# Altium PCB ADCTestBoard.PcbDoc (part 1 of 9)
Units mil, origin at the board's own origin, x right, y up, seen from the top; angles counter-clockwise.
Board outline 11022.62 x 9187 mil, 8 copper layers (TopLayer, InternalPlane1, InternalPlane2, InternalPlane3, InternalPlane4, InternalPlane5, MidLayer1, BottomLayer), stack 103.8 mil thick; 1282 components, 637 nets, 4473 pads, 1306 vias.
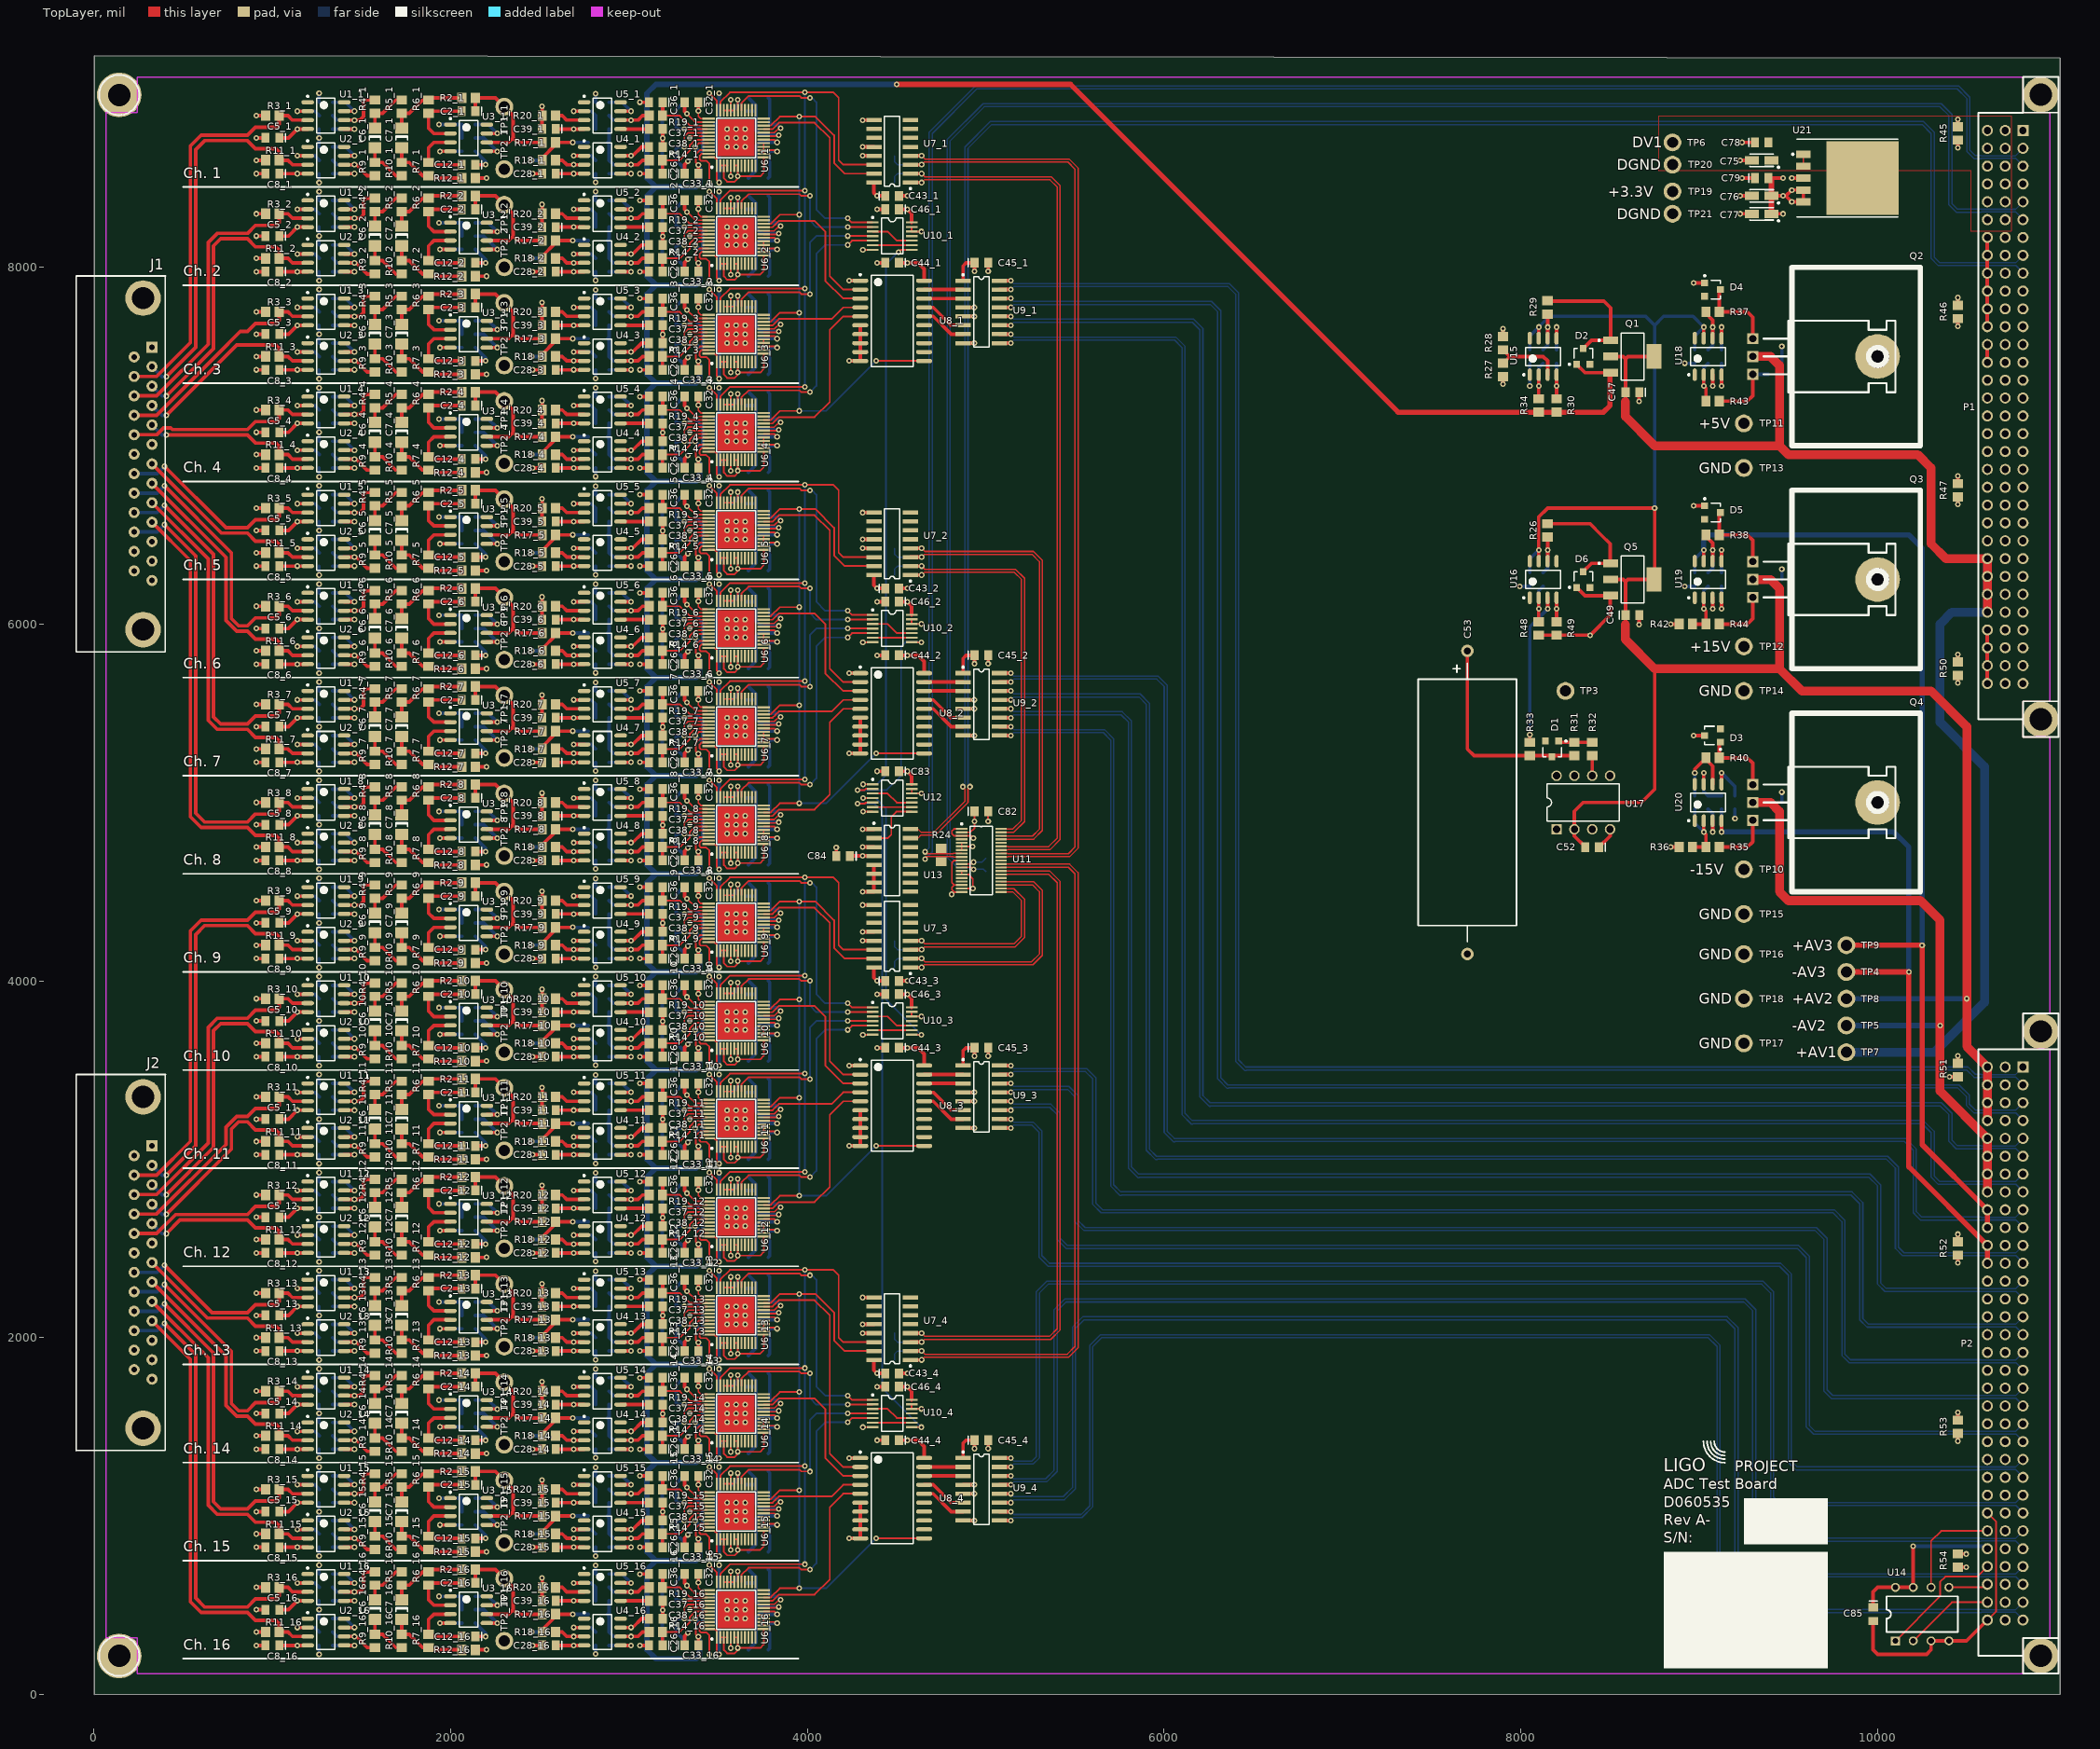
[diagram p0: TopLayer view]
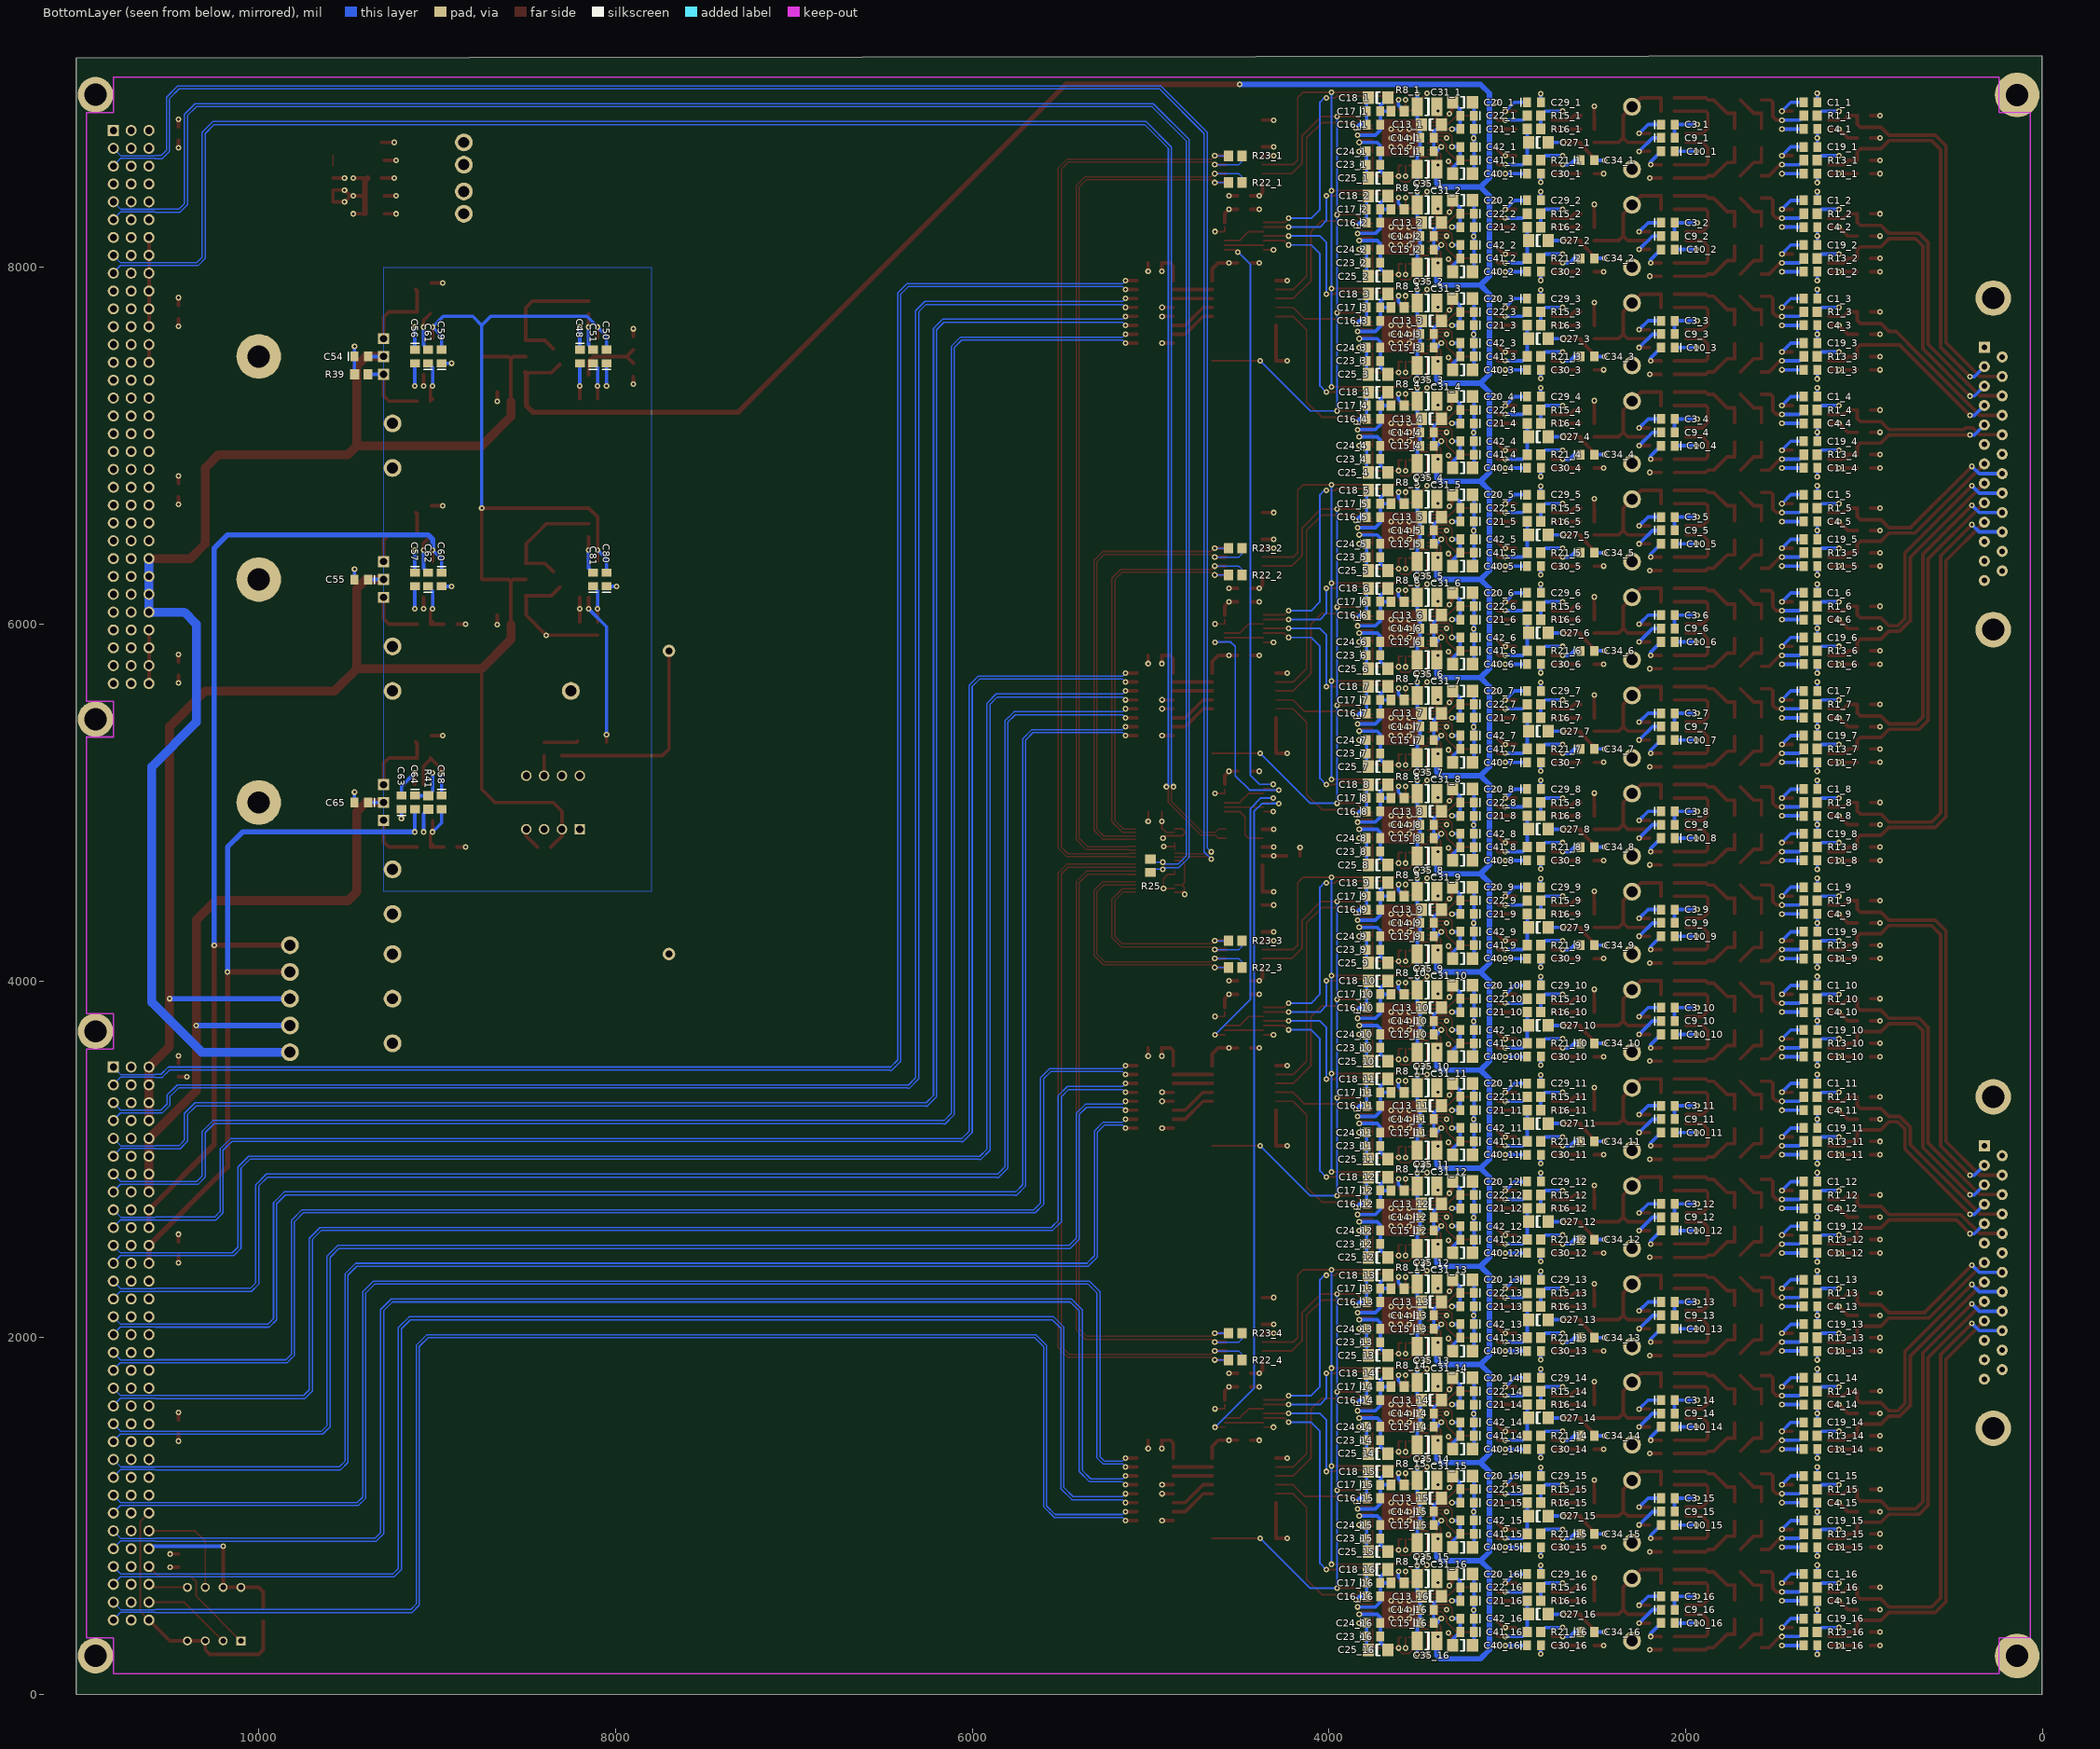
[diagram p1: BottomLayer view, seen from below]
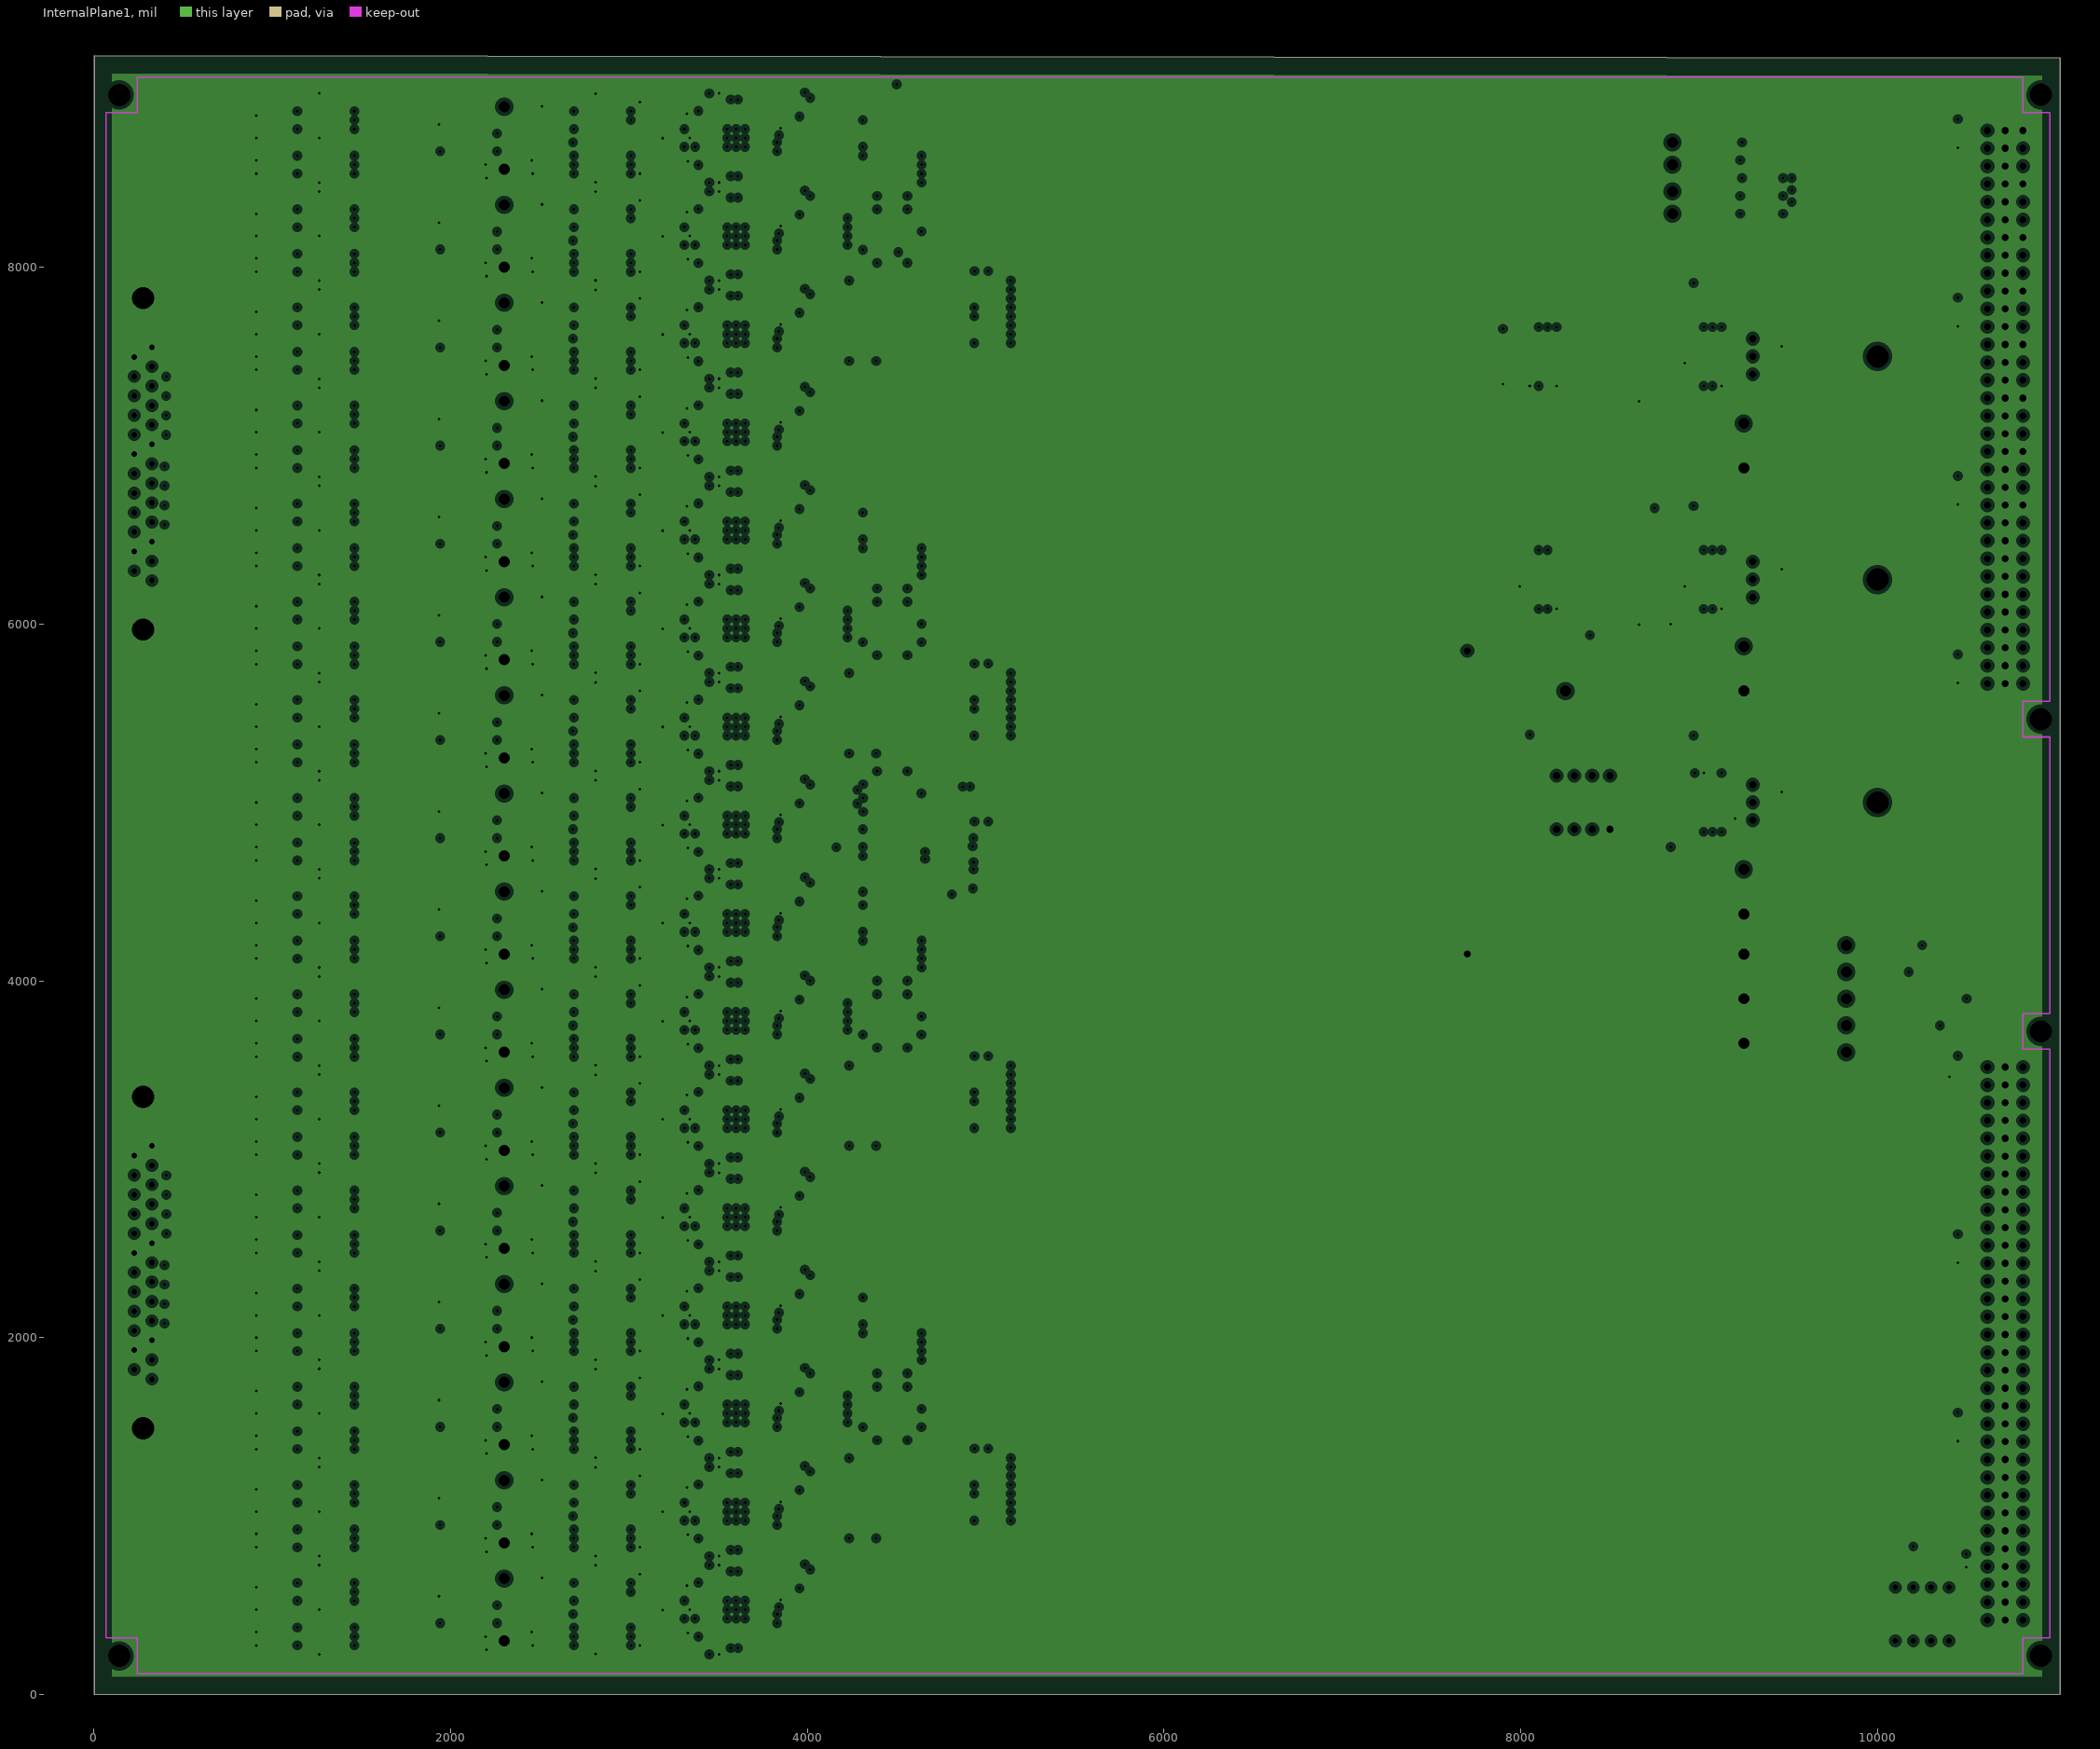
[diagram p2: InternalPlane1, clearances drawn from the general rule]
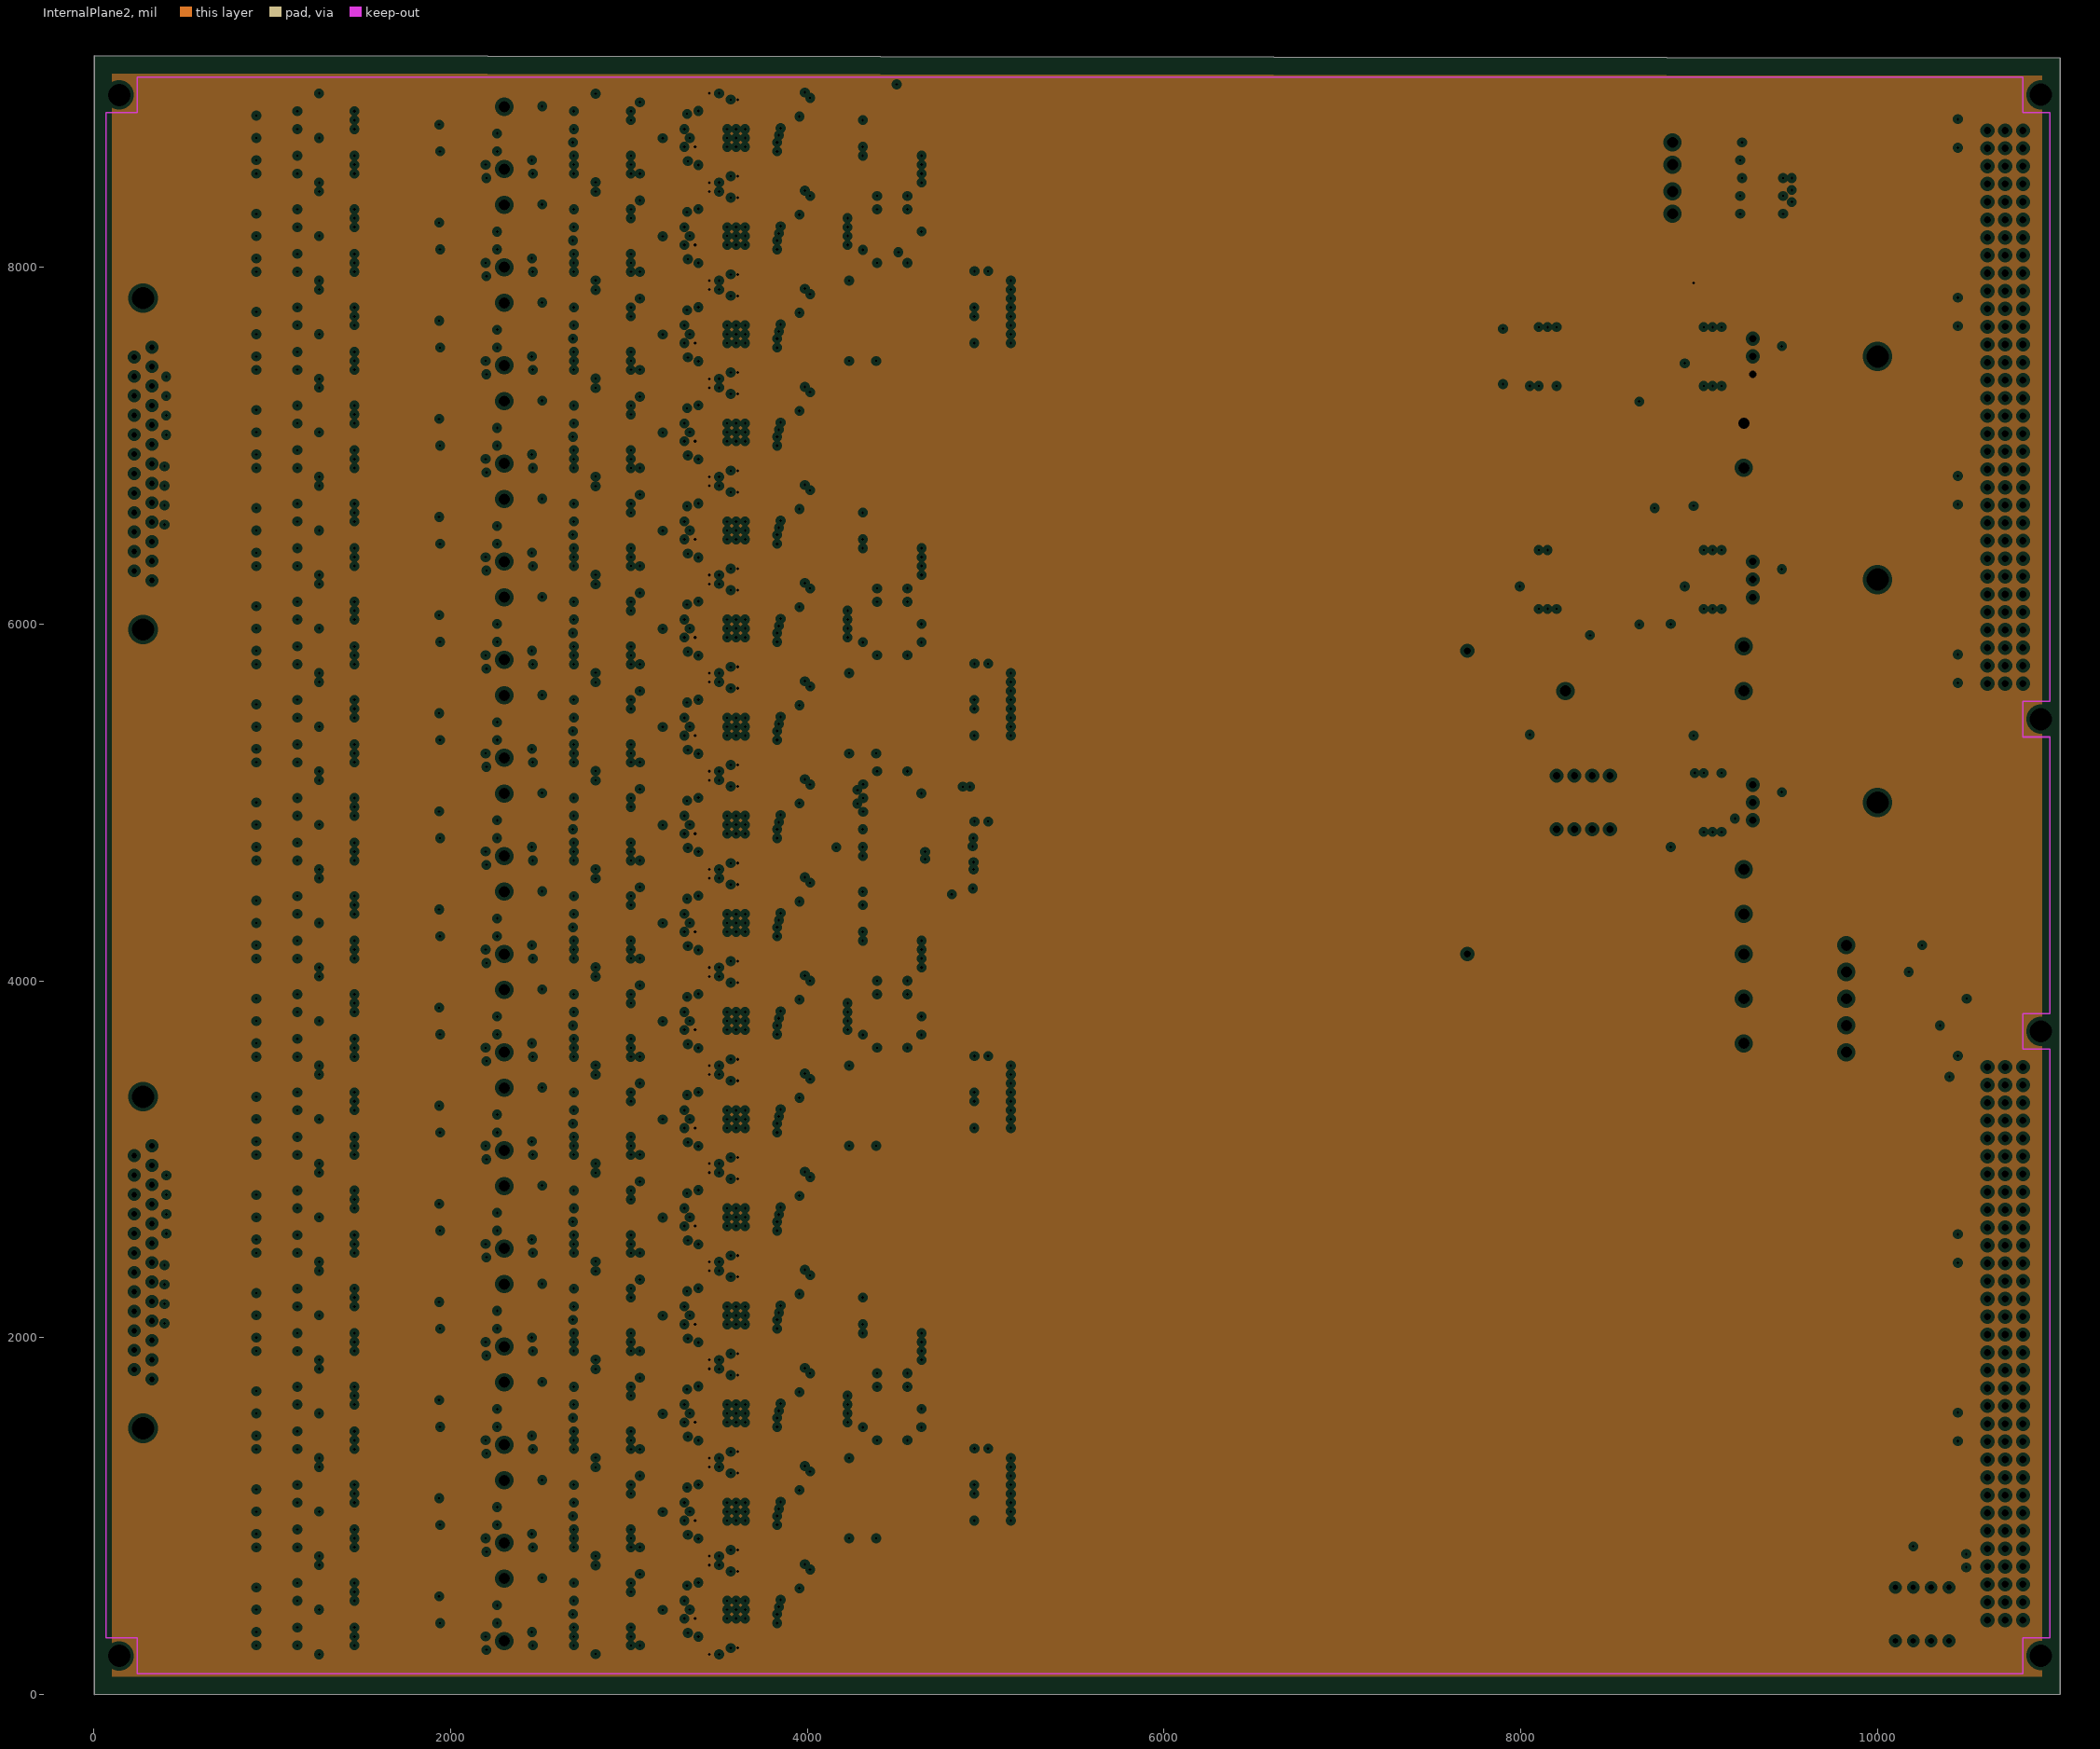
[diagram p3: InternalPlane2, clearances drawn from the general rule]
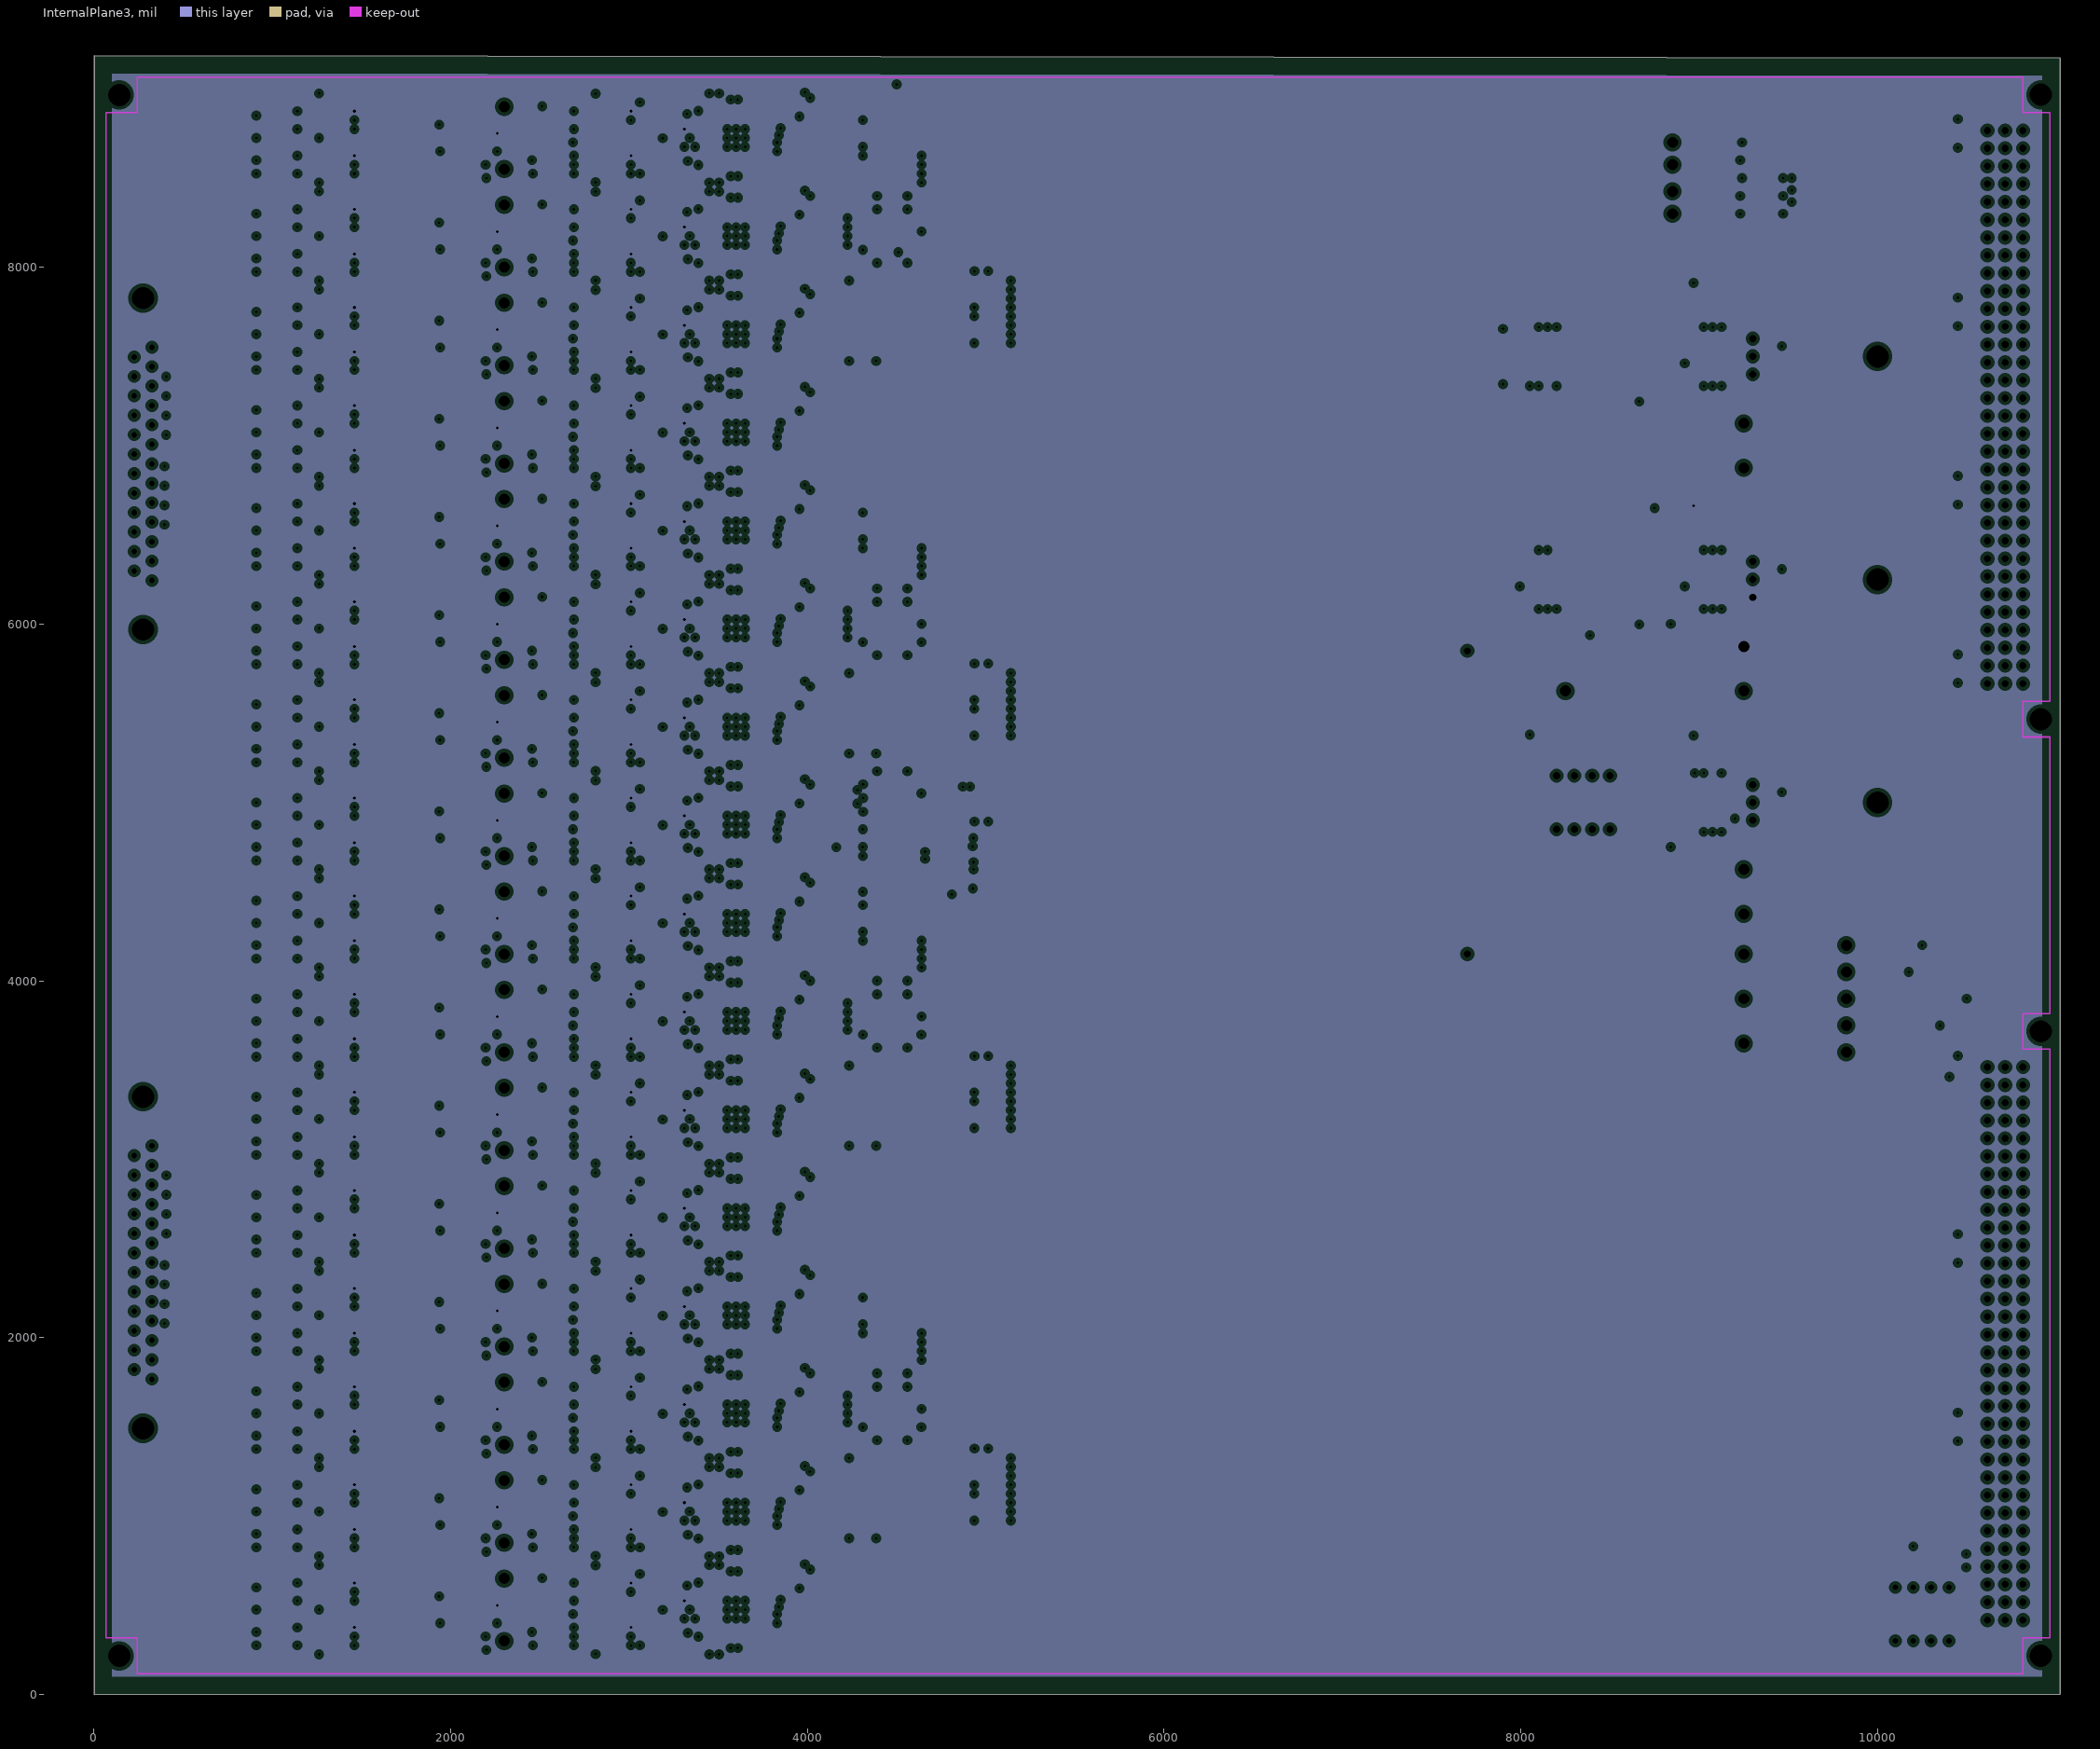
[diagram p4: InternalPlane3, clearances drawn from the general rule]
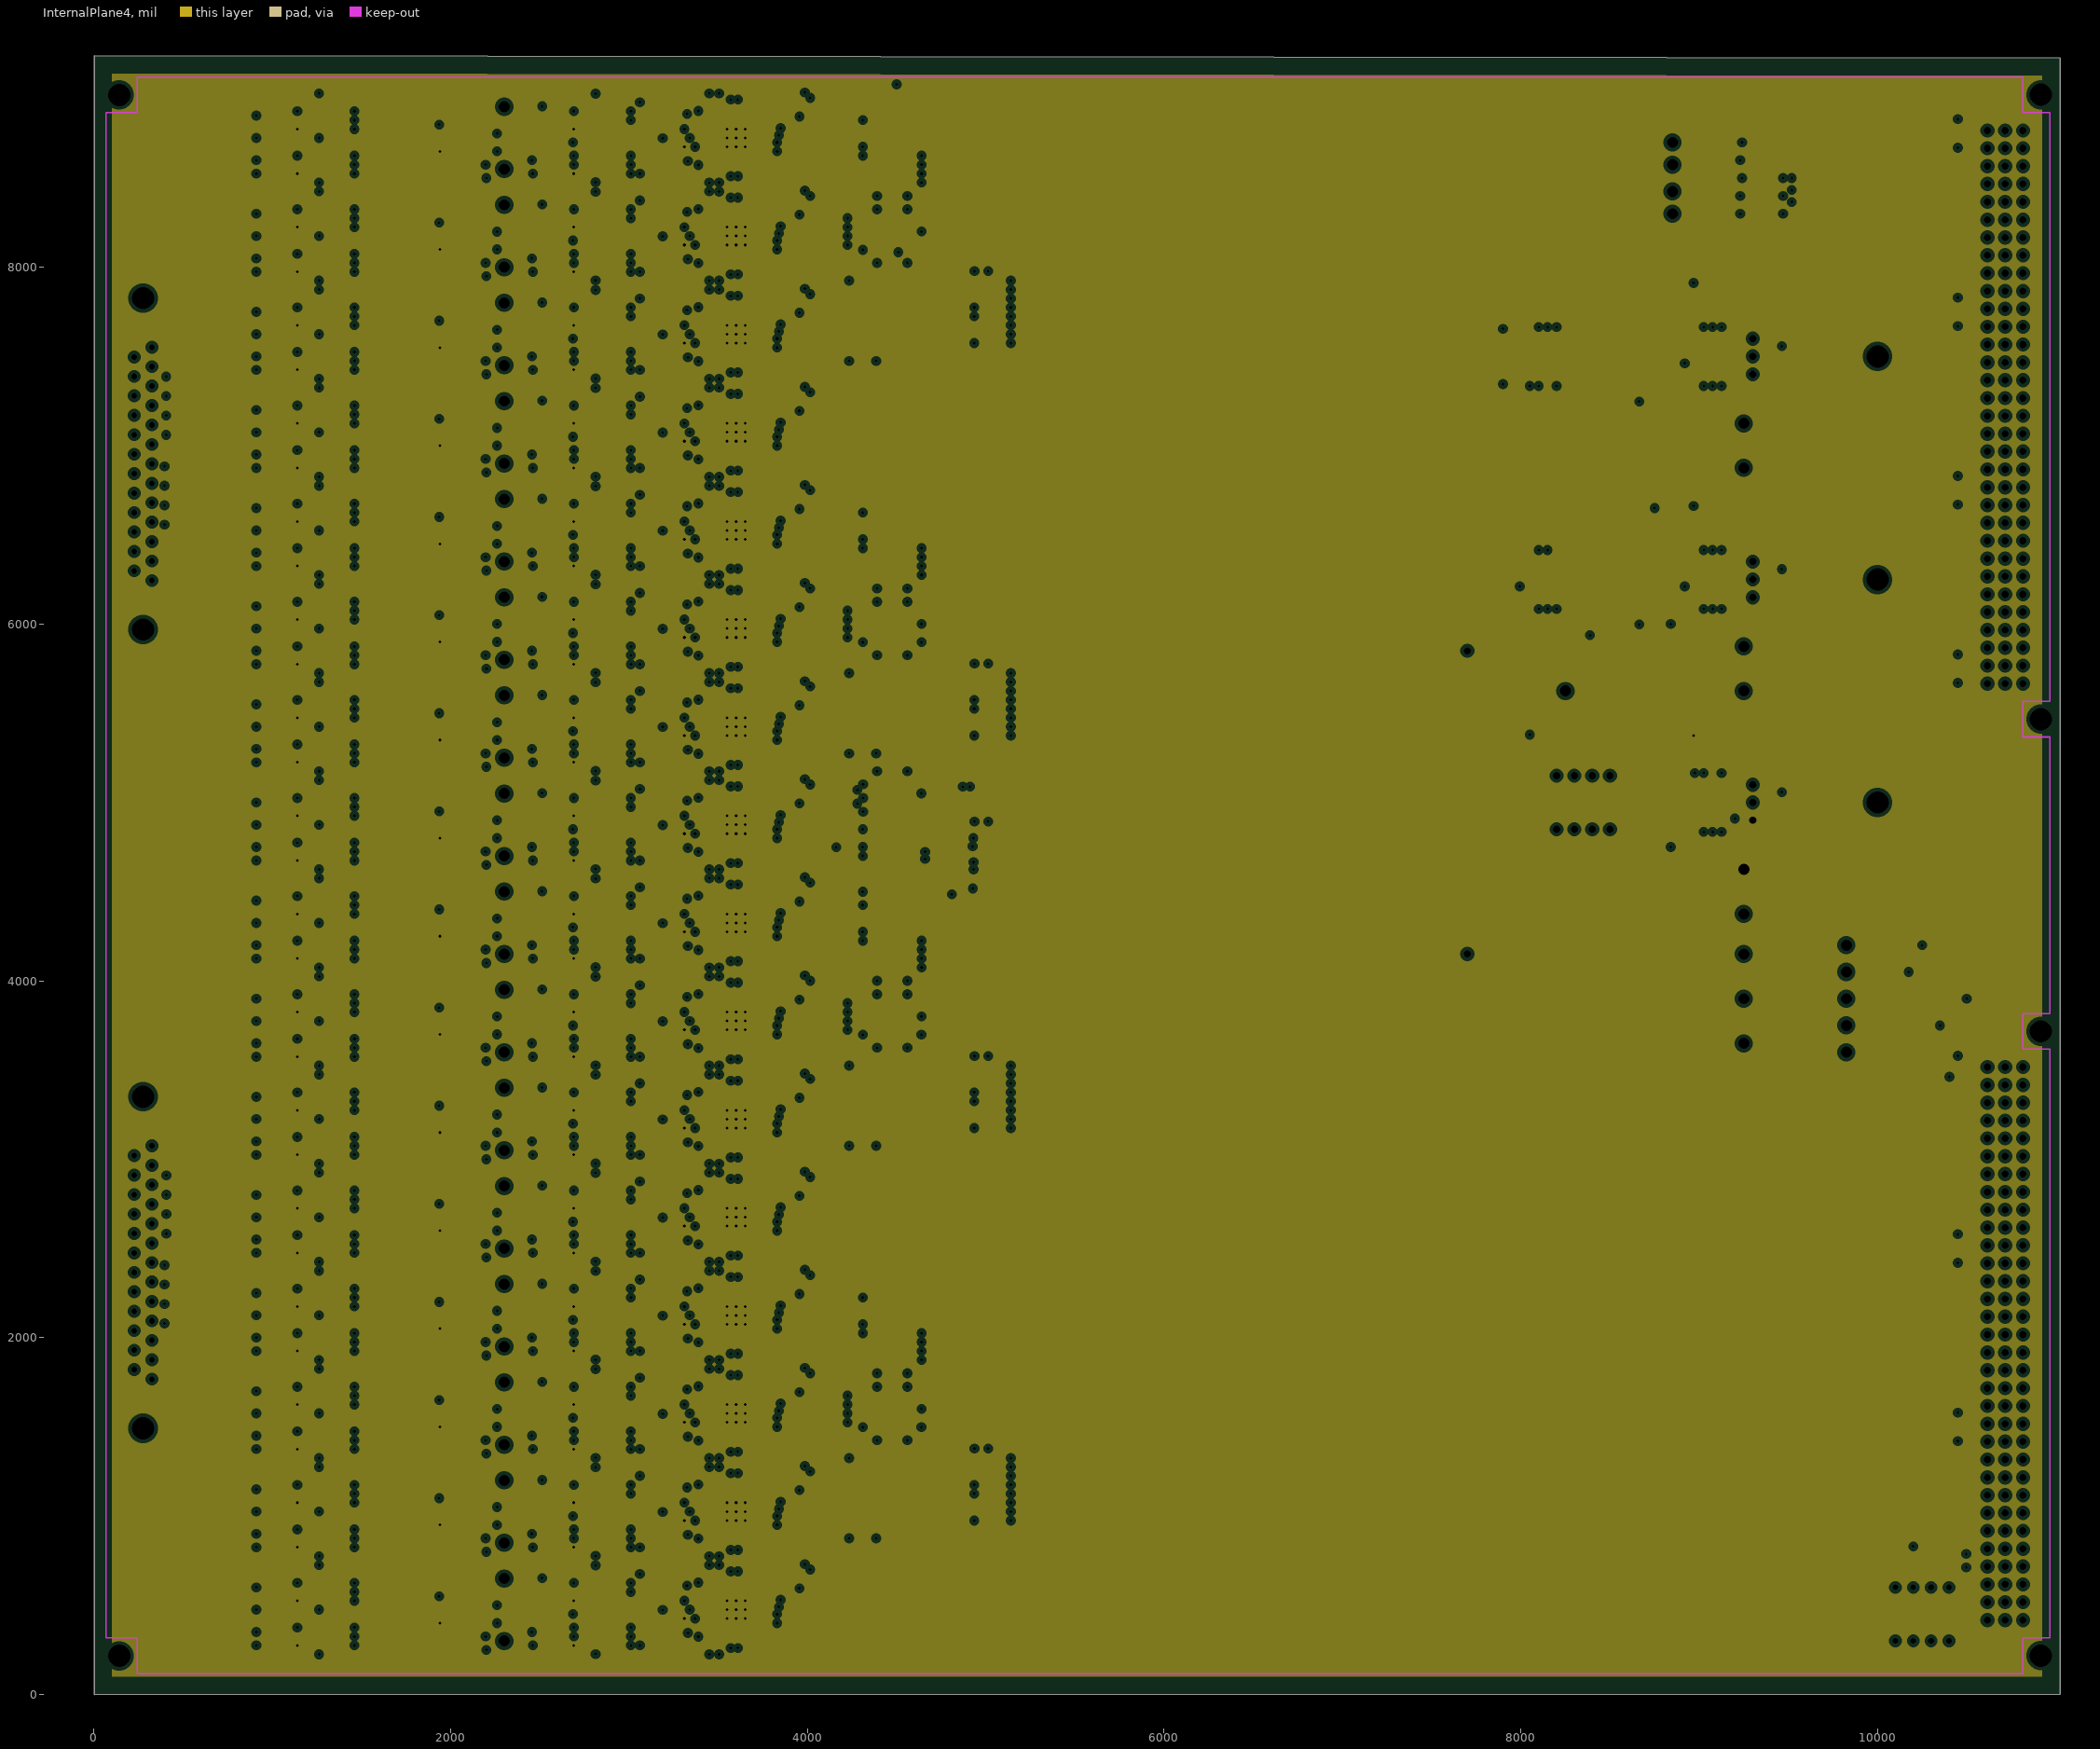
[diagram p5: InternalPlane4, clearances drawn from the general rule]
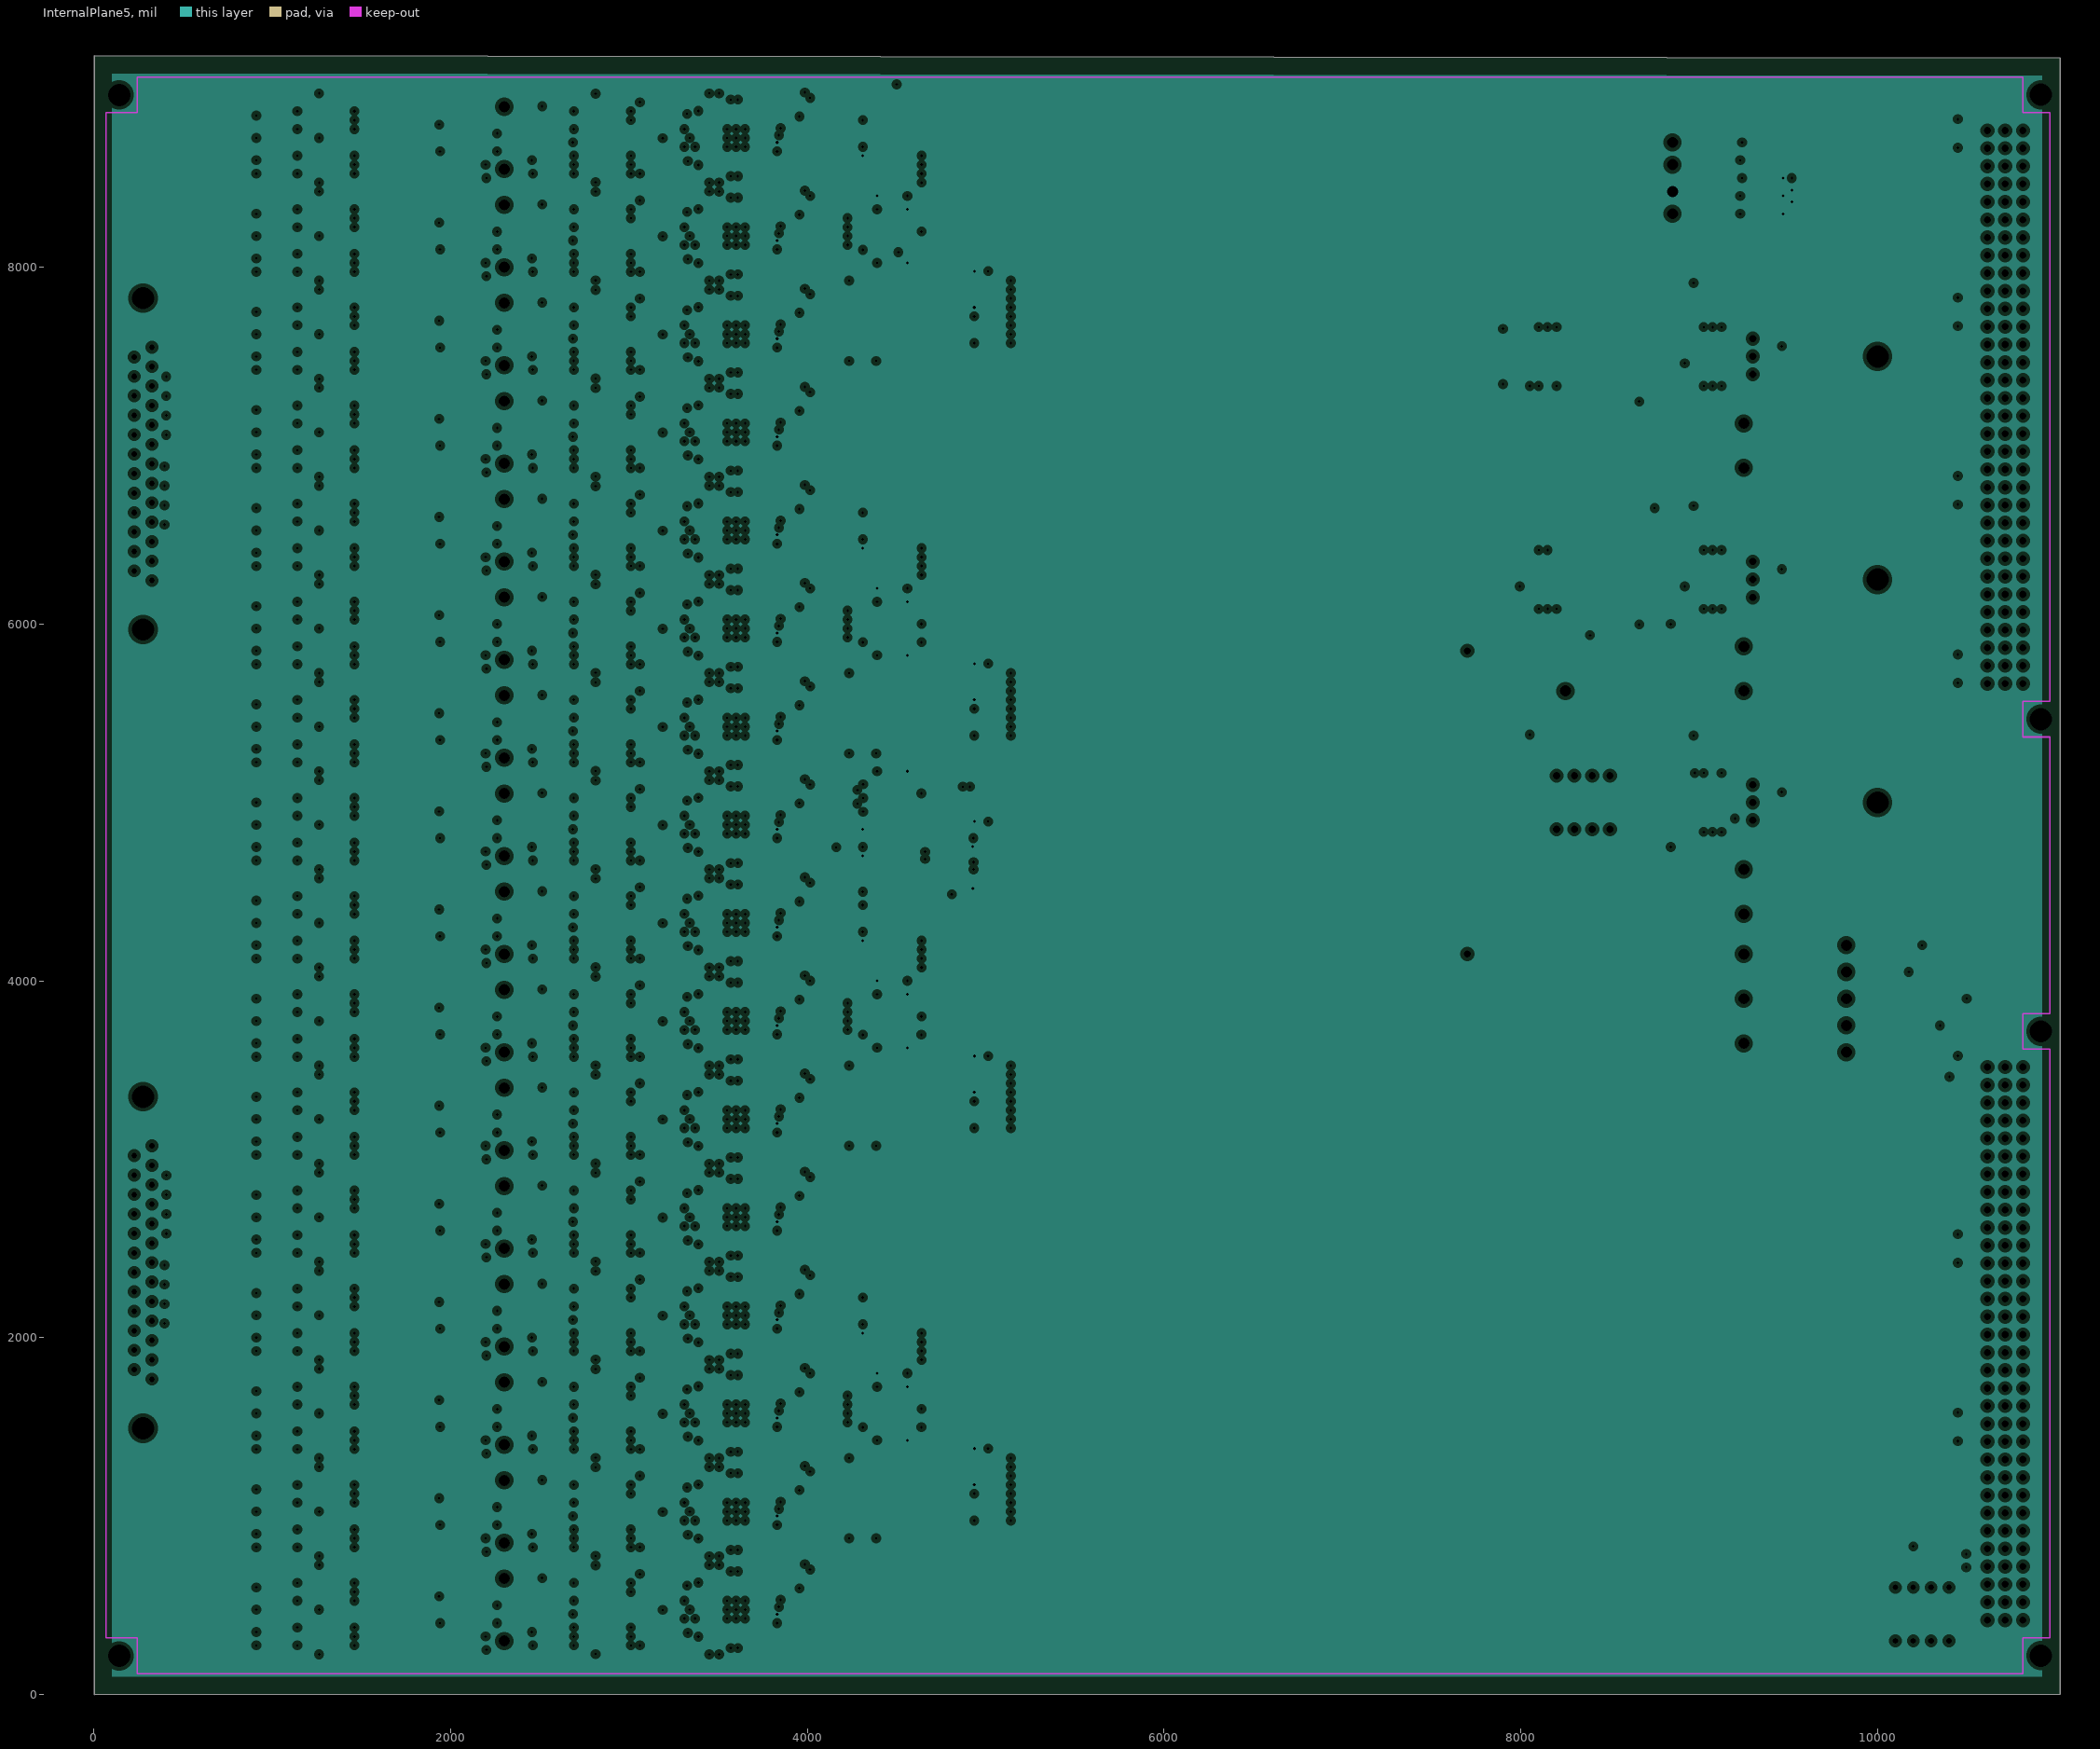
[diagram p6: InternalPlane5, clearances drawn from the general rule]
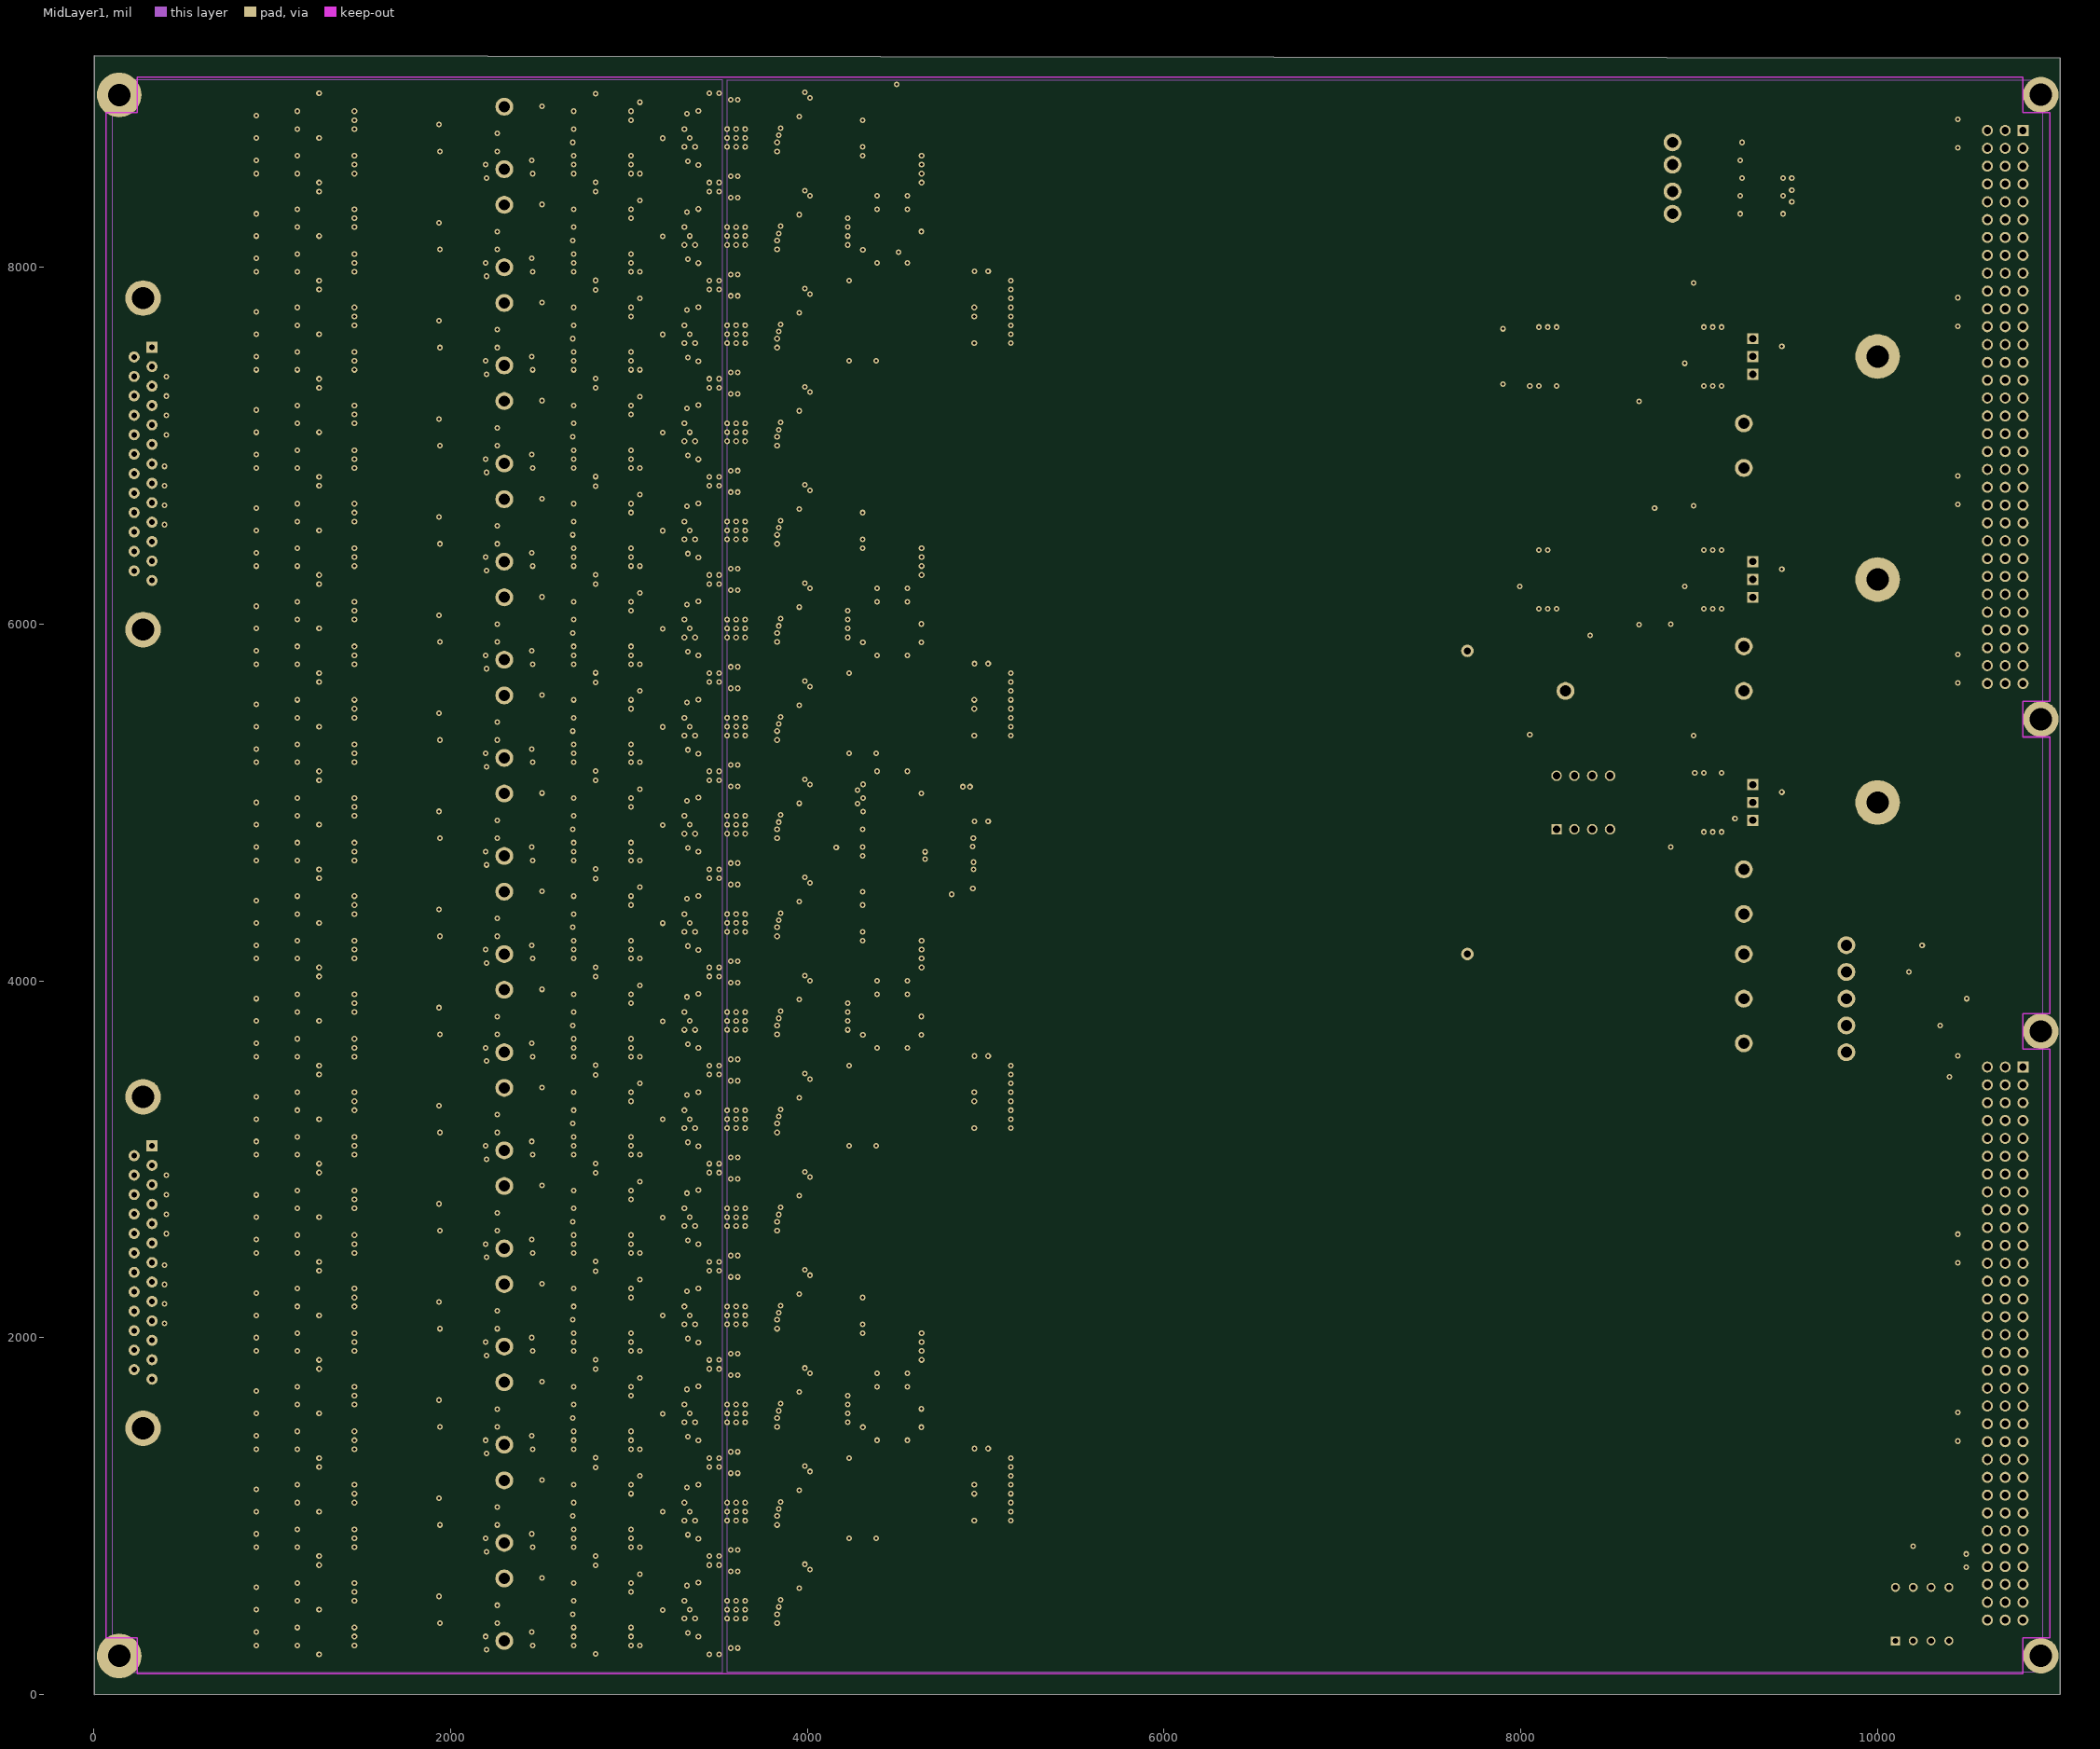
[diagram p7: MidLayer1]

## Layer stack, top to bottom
TopLayer: signal copper 1.4
Dielectric: prepreg 6.4, FR-4, Dk 4.8
InternalPlane1: plane copper 1.4, net GND
Dielectric: core 21, FR-4, Dk 4.8
InternalPlane2: plane copper 1.4, net +5V
Dielectric: prepreg 21, FR-4, Dk 4.8
InternalPlane3: plane copper 1.4, net +15V
Dielectric: core 12.6, FR-4, Dk 4.8
InternalPlane4: plane copper 1.4, net -15V
Dielectric: prepreg 12.6, FR-4, Dk 4.8
InternalPlane5: plane copper 1.4, net +3.3V
Dielectric: core 6.4, FR-4, Dk 4.8
MidLayer1: signal copper 1.4
Dielectric: prepreg 12.6, FR-4, Dk 4.8
BottomLayer: signal copper 1.4

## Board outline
11023.62,0 11023.62,4724.41 11023.62,9173.23 1,9186 1,-1

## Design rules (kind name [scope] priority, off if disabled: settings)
Clearance "DV1 Poly" [(InNet('DV1') AND InPoly)] p1: gap=15
Clearance "General Poly" [InPoly] p2: gap=20
Clearance [All] p3: gap=7
ComponentClearance [All] p1 off: gap=10 collisioncheckmode=0 verticalgap=10
DiffPairsRouting [All] p1: maxlimit=9 minlimit=9 mostfreqgap=9 maxuncoupledlength=500
FanoutControl Fanout_Small [(CompPinCount < 5)] p1 off: bgadir=Out bgaviamode=Centered fanoutstyle=Auto fanoutdirection=OutThenIn viagrid=1 // Fanout_Small (Default Rule)
FanoutControl Fanout_Default [All] p2 off: bgadir=Out bgaviamode=Centered fanoutstyle=Auto fanoutdirection=Alternating viagrid=1 // Fanout_Default (Default Rule)
FanoutControl Fanout_SOIC [IsSOIC] p3 off: bgadir=Out bgaviamode=Centered fanoutstyle=Auto fanoutdirection=Alternating viagrid=1 // Fanout_SOIC (Default Rule)
FanoutControl Fanout_BGA [IsBGA] p4 off: bgadir=Out bgaviamode=Centered fanoutstyle=Auto fanoutdirection=Alternating viagrid=1 // Fanout_BGA (Default Rule)
FanoutControl Fanout_LCC [IsLCC] p5 off: bgadir=Out bgaviamode=Centered fanoutstyle=Auto fanoutdirection=Alternating viagrid=1 // Fanout_LCC (Default Rule)
HoleSize [All] p1: absolutevalues=TRUE maxlimit=250 minlimit=10 maxpercent=80.000 minpercent=20.000
MinimumAnnularRing [All] p1: minimumring=8
PlaneClearance [All] p1: clearance=20
PlaneConnect [(InPadClass('New Class'))] p1: planeconnectstyle=Relief reliefexpansion=10 reliefentries=4 reliefconductorwidth=10 reliefairgap=10
PlaneConnect PlaneConnect_1 [All] p2: planeconnectstyle=Relief reliefexpansion=20 reliefentries=4 reliefconductorwidth=10 reliefairgap=10
PolygonConnect [All] p1: connectstyle=Relief reliefconductorwidth=10 reliefentries=4 polygonreliefangle="90 Angle"
RoomDefinition 12 [InComponentClass('12')] p1: confinementstyle=ConfineIn formatcopy=TRUE lockcomponents=FALSE outline 850,6250 850,6800 4050,6800 4050,6250
RoomDefinition 13 [InComponentClass('13')] p2: confinementstyle=ConfineIn formatcopy=TRUE lockcomponents=FALSE outline 850,4050 850,4600 4050,4600 4050,4050
RoomDefinition 14 [InComponentClass('14')] p3: confinementstyle=ConfineIn formatcopy=TRUE lockcomponents=FALSE outline 850,1850 850,2400 4050,2400 4050,1850
RoomDefinition 21 [InComponentClass('21')] p4: confinementstyle=ConfineIn formatcopy=TRUE lockcomponents=FALSE outline 850,7900 850,8450 4050,8450 4050,7900
RoomDefinition 22 [InComponentClass('22')] p5: confinementstyle=ConfineIn formatcopy=TRUE lockcomponents=FALSE outline 850,5700 850,6250 4050,6250 4050,5700
RoomDefinition 23 [InComponentClass('23')] p6: confinementstyle=ConfineIn formatcopy=TRUE lockcomponents=FALSE outline 850,3500 850,4050 4050,4050 4050,3500
RoomDefinition 24 [InComponentClass('24')] p7: confinementstyle=ConfineIn formatcopy=TRUE lockcomponents=FALSE outline 850,1300 850,1850 4050,1850 4050,1300
RoomDefinition 31 [InComponentClass('31')] p8: confinementstyle=ConfineIn formatcopy=TRUE lockcomponents=FALSE outline 850,7350 850,7900 4050,7900 4050,7350
RoomDefinition 32 [InComponentClass('32')] p9: confinementstyle=ConfineIn formatcopy=TRUE lockcomponents=FALSE outline 850,5150 850,5700 4050,5700 4050,5150
RoomDefinition 33 [InComponentClass('33')] p10: confinementstyle=ConfineIn formatcopy=TRUE lockcomponents=FALSE outline 850,2950 850,3500 4050,3500 4050,2950
RoomDefinition 34 [InComponentClass('34')] p11: confinementstyle=ConfineIn formatcopy=TRUE lockcomponents=FALSE outline 850,750 850,1300 4050,1300 4050,750
RoomDefinition 41 [InComponentClass('41')] p12: confinementstyle=ConfineIn formatcopy=TRUE lockcomponents=FALSE outline 850,6800 850,7350 4050,7350 4050,6800
RoomDefinition 42 [InComponentClass('42')] p13: confinementstyle=ConfineIn formatcopy=TRUE lockcomponents=FALSE outline 850,4600 850,5150 4050,5150 4050,4600
RoomDefinition 43 [InComponentClass('43')] p14: confinementstyle=ConfineIn formatcopy=TRUE lockcomponents=FALSE outline 850,2400 850,2950 4050,2950 4050,2400
RoomDefinition 44 [InComponentClass('44')] p15: confinementstyle=ConfineIn formatcopy=TRUE lockcomponents=FALSE outline 850,200 850,750 4050,750 4050,200
RoomDefinition 4 [InComponentClass('4')] p16: confinementstyle=ConfineIn formatcopy=TRUE lockcomponents=FALSE outline 3950,2400 5250,2400 5250,200 3950,200
RoomDefinition 2 [InComponentClass('2')] p17: confinementstyle=ConfineIn formatcopy=TRUE lockcomponents=FALSE outline 3950,6800 5250,6800 5250,4600 3950,4600
RoomDefinition 3 [InComponentClass('3')] p18: confinementstyle=ConfineIn formatcopy=TRUE lockcomponents=FALSE outline 3950,4600 5250,4600 5250,2400 3950,2400
RoomDefinition 1 [InComponentClass('1')] p19: confinementstyle=ConfineIn formatcopy=TRUE lockcomponents=FALSE outline 3950,9000 5250,9000 5250,6800 3950,6800
RoomDefinition Interface [InComponentClass('Interface')] p20: confinementstyle=ConfineOut formatcopy=TRUE lockcomponents=FALSE outline 12000,1500 12000,2000 12500,2000 12500,1500
RoomDefinition Power [InComponentClass('Power')] p21: confinementstyle=ConfineOut formatcopy=TRUE lockcomponents=FALSE outline 12000,1000 12000,1500 12500,1500 12500,1000
RoomDefinition ADCTB_Overview1 [InComponentClass('ADCTB_Overview1')] p22: confinementstyle=ConfineOut formatcopy=TRUE lockcomponents=FALSE outline 12000,2000 12000,2500 12500,2500 12500,2000
RoomDefinition 11 [InComponentClass('11')] p23: confinementstyle=ConfineIn formatcopy=TRUE lockcomponents=FALSE outline 850,8450 850,9000 4050,9000 4050,8450
RoutingVias [All] p1: holewidth=20 width=40 viastyle="Through Hole" minholewidth=5 minwidth=25 maxholewidth=50 maxwidth=70
SolderMaskExpansion [All] p1: expansion=4
TestPointUsage [All] p1: valid=0 allowmultiple=FALSE
Testpoint [All] p1: side=15 testpointundercomponent=TRUE minsize=40 maxsize=100 preferedsize=60 minholesize=0 maxholesize=40 preferedholesize=32 testpointgrid=1 style=1023 order=0-112345678
Testpoint Testpoint_1 [All] p2: side=7 testpointundercomponent=TRUE minsize=40 maxsize=100 preferedsize=60 minholesize=20 maxholesize=40 preferedholesize=32 testpointgrid=1 style=1001 order=0123456789
Width [All] p1: maxlimit=100 minlimit=5 preferedwidth=10 minimp=50.000000 maximp=50.000000 favimp=50.000000
9 further rules are at their usual default settings.

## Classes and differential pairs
pad class "New Class": Free-0
component class ADCTB_Overview1: J1 J2
component class Power: C47 C48 C49 C50 C51 C52 C53 C54 C55 C56 C57 C58 C59 C60 C61 C62 C63 C64 C65 C75 C76 C77 C78 C79 C80 C81 D1 D2 D3 D4 D5 D6 Q1 Q2 Q3 Q4 Q5 R26 R27 R28 R29 R30 R31 R32 R33 R34 R35 R36 R37 R38 R39 R40 R41 R42 R43 R44 R45 R46 R47 R48 R49 R50 R51 R52 R53 R54 TP3 TP4 TP5 TP6 TP7 TP8 TP9 TP10 TP11 TP12 TP13 TP14 TP15 TP16 TP17 TP18 TP19 TP20 TP21 U15 U16 U17 U18 U19 U20 U21
component class 44: C1_16 C2_16 C3_16 C4_16 C5_16 C6_16 C7_16 C8_16 C9_16 C10_16 C11_16 C12_16 C13_16 C14_16 C15_16 C16_16 C17_16 C18_16 C19_16 C20_16 C21_16 C22_16 C23_16 C24_16 C25_16 C26_16 C27_16 C28_16 C29_16 C30_16 C31_16 C32_16 C33_16 C34_16 C35_16 C36_16 C37_16 C38_16 C39_16 C40_16 C41_16 C42_16 R1_16 R2_16 R3_16 R4_16 R5_16 R6_16 R7_16 R8_16 R9_16 R10_16 R11_16 R12_16 R13_16 R14_16 R15_16 R16_16 R17_16 R18_16 R19_16 R20_16 R21_16 TP1_16 TP2_16 U1_16 U2_16 U3_16 U4_16 U5_16 U6_16
component class 43: C1_12 C2_12 C3_12 C4_12 C5_12 C6_12 C7_12 C8_12 C9_12 C10_12 C11_12 C12_12 C13_12 C14_12 C15_12 C16_12 C17_12 C18_12 C19_12 C20_12 C21_12 C22_12 C23_12 C24_12 C25_12 C26_12 C27_12 C28_12 C29_12 C30_12 C31_12 C32_12 C33_12 C34_12 C35_12 C36_12 C37_12 C38_12 C39_12 C40_12 C41_12 C42_12 R1_12 R2_12 R3_12 R4_12 R5_12 R6_12 R7_12 R8_12 R9_12 R10_12 R11_12 R12_12 R13_12 R14_12 R15_12 R16_12 R17_12 R18_12 R19_12 R20_12 R21_12 TP1_12 TP2_12 U1_12 U2_12 U3_12 U4_12 U5_12 U6_12
component class 42: C1_8 C2_8 C3_8 C4_8 C5_8 C6_8 C7_8 C8_8 C9_8 C10_8 C11_8 C12_8 C13_8 C14_8 C15_8 C16_8 C17_8 C18_8 C19_8 C20_8 C21_8 C22_8 C23_8 C24_8 C25_8 C26_8 C27_8 C28_8 C29_8 C30_8 C31_8 C32_8 C33_8 C34_8 C35_8 C36_8 C37_8 C38_8 C39_8 C40_8 C41_8 C42_8 R1_8 R2_8 R3_8 R4_8 R5_8 R6_8 R7_8 R8_8 R9_8 R10_8 R11_8 R12_8 R13_8 R14_8 R15_8 R16_8 R17_8 R18_8 R19_8 R20_8 R21_8 TP1_8 TP2_8 U1_8 U2_8 U3_8 U4_8 U5_8 U6_8
component class 41: C1_4 C2_4 C3_4 C4_4 C5_4 C6_4 C7_4 C8_4 C9_4 C10_4 C11_4 C12_4 C13_4 C14_4 C15_4 C16_4 C17_4 C18_4 C19_4 C20_4 C21_4 C22_4 C23_4 C24_4 C25_4 C26_4 C27_4 C28_4 C29_4 C30_4 C31_4 C32_4 C33_4 C34_4 C35_4 C36_4 C37_4 C38_4 C39_4 C40_4 C41_4 C42_4 R1_4 R2_4 R3_4 R4_4 R5_4 R6_4 R7_4 R8_4 R9_4 R10_4 R11_4 R12_4 R13_4 R14_4 R15_4 R16_4 R17_4 R18_4 R19_4 R20_4 R21_4 TP1_4 TP2_4 U1_4 U2_4 U3_4 U4_4 U5_4 U6_4
component class 34: C1_15 C2_15 C3_15 C4_15 C5_15 C6_15 C7_15 C8_15 C9_15 C10_15 C11_15 C12_15 C13_15 C14_15 C15_15 C16_15 C17_15 C18_15 C19_15 C20_15 C21_15 C22_15 C23_15 C24_15 C25_15 C26_15 C27_15 C28_15 C29_15 C30_15 C31_15 C32_15 C33_15 C34_15 C35_15 C36_15 C37_15 C38_15 C39_15 C40_15 C41_15 C42_15 R1_15 R2_15 R3_15 R4_15 R5_15 R6_15 R7_15 R8_15 R9_15 R10_15 R11_15 R12_15 R13_15 R14_15 R15_15 R16_15 R17_15 R18_15 R19_15 R20_15 R21_15 TP1_15 TP2_15 U1_15 U2_15 U3_15 U4_15 U5_15 U6_15
component class 33: C1_11 C2_11 C3_11 C4_11 C5_11 C6_11 C7_11 C8_11 C9_11 C10_11 C11_11 C12_11 C13_11 C14_11 C15_11 C16_11 C17_11 C18_11 C19_11 C20_11 C21_11 C22_11 C23_11 C24_11 C25_11 C26_11 C27_11 C28_11 C29_11 C30_11 C31_11 C32_11 C33_11 C34_11 C35_11 C36_11 C37_11 C38_11 C39_11 C40_11 C41_11 C42_11 R1_11 R2_11 R3_11 R4_11 R5_11 R6_11 R7_11 R8_11 R9_11 R10_11 R11_11 R12_11 R13_11 R14_11 R15_11 R16_11 R17_11 R18_11 R19_11 R20_11 R21_11 TP1_11 TP2_11 U1_11 U2_11 U3_11 U4_11 U5_11 U6_11
component class 32: C1_7 C2_7 C3_7 C4_7 C5_7 C6_7 C7_7 C8_7 C9_7 C10_7 C11_7 C12_7 C13_7 C14_7 C15_7 C16_7 C17_7 C18_7 C19_7 C20_7 C21_7 C22_7 C23_7 C24_7 C25_7 C26_7 C27_7 C28_7 C29_7 C30_7 C31_7 C32_7 C33_7 C34_7 C35_7 C36_7 C37_7 C38_7 C39_7 C40_7 C41_7 C42_7 R1_7 R2_7 R3_7 R4_7 R5_7 R6_7 R7_7 R8_7 R9_7 R10_7 R11_7 R12_7 R13_7 R14_7 R15_7 R16_7 R17_7 R18_7 R19_7 R20_7 R21_7 TP1_7 TP2_7 U1_7 U2_7 U3_7 U4_7 U5_7 U6_7
component class 31: C1_3 C2_3 C3_3 C4_3 C5_3 C6_3 C7_3 C8_3 C9_3 C10_3 C11_3 C12_3 C13_3 C14_3 C15_3 C16_3 C17_3 C18_3 C19_3 C20_3 C21_3 C22_3 C23_3 C24_3 C25_3 C26_3 C27_3 C28_3 C29_3 C30_3 C31_3 C32_3 C33_3 C34_3 C35_3 C36_3 C37_3 C38_3 C39_3 C40_3 C41_3 C42_3 R1_3 R2_3 R3_3 R4_3 R5_3 R6_3 R7_3 R8_3 R9_3 R10_3 R11_3 R12_3 R13_3 R14_3 R15_3 R16_3 R17_3 R18_3 R19_3 R20_3 R21_3 TP1_3 TP2_3 U1_3 U2_3 U3_3 U4_3 U5_3 U6_3
component class 24: C1_14 C2_14 C3_14 C4_14 C5_14 C6_14 C7_14 C8_14 C9_14 C10_14 C11_14 C12_14 C13_14 C14_14 C15_14 C16_14 C17_14 C18_14 C19_14 C20_14 C21_14 C22_14 C23_14 C24_14 C25_14 C26_14 C27_14 C28_14 C29_14 C30_14 C31_14 C32_14 C33_14 C34_14 C35_14 C36_14 C37_14 C38_14 C39_14 C40_14 C41_14 C42_14 R1_14 R2_14 R3_14 R4_14 R5_14 R6_14 R7_14 R8_14 R9_14 R10_14 R11_14 R12_14 R13_14 R14_14 R15_14 R16_14 R17_14 R18_14 R19_14 R20_14 R21_14 TP1_14 TP2_14 U1_14 U2_14 U3_14 U4_14 U5_14 U6_14
component class 23: C1_10 C2_10 C3_10 C4_10 C5_10 C6_10 C7_10 C8_10 C9_10 C10_10 C11_10 C12_10 C13_10 C14_10 C15_10 C16_10 C17_10 C18_10 C19_10 C20_10 C21_10 C22_10 C23_10 C24_10 C25_10 C26_10 C27_10 C28_10 C29_10 C30_10 C31_10 C32_10 C33_10 C34_10 C35_10 C36_10 C37_10 C38_10 C39_10 C40_10 C41_10 C42_10 R1_10 R2_10 R3_10 R4_10 R5_10 R6_10 R7_10 R8_10 R9_10 R10_10 R11_10 R12_10 R13_10 R14_10 R15_10 R16_10 R17_10 R18_10 R19_10 R20_10 R21_10 TP1_10 TP2_10 U1_10 U2_10 U3_10 U4_10 U5_10 U6_10
component class 22: C1_6 C2_6 C3_6 C4_6 C5_6 C6_6 C7_6 C8_6 C9_6 C10_6 C11_6 C12_6 C13_6 C14_6 C15_6 C16_6 C17_6 C18_6 C19_6 C20_6 C21_6 C22_6 C23_6 C24_6 C25_6 C26_6 C27_6 C28_6 C29_6 C30_6 C31_6 C32_6 C33_6 C34_6 C35_6 C36_6 C37_6 C38_6 C39_6 C40_6 C41_6 C42_6 R1_6 R2_6 R3_6 R4_6 R5_6 R6_6 R7_6 R8_6 R9_6 R10_6 R11_6 R12_6 R13_6 R14_6 R15_6 R16_6 R17_6 R18_6 R19_6 R20_6 R21_6 TP1_6 TP2_6 U1_6 U2_6 U3_6 U4_6 U5_6 U6_6
component class 21: C1_2 C2_2 C3_2 C4_2 C5_2 C6_2 C7_2 C8_2 C9_2 C10_2 C11_2 C12_2 C13_2 C14_2 C15_2 C16_2 C17_2 C18_2 C19_2 C20_2 C21_2 C22_2 C23_2 C24_2 C25_2 C26_2 C27_2 C28_2 C29_2 C30_2 C31_2 C32_2 C33_2 C34_2 C35_2 C36_2 C37_2 C38_2 C39_2 C40_2 C41_2 C42_2 R1_2 R2_2 R3_2 R4_2 R5_2 R6_2 R7_2 R8_2 R9_2 R10_2 R11_2 R12_2 R13_2 R14_2 R15_2 R16_2 R17_2 R18_2 R19_2 R20_2 R21_2 TP1_2 TP2_2 U1_2 U2_2 U3_2 U4_2 U5_2 U6_2
component class 14: C1_13 C2_13 C3_13 C4_13 C5_13 C6_13 C7_13 C8_13 C9_13 C10_13 C11_13 C12_13 C13_13 C14_13 C15_13 C16_13 C17_13 C18_13 C19_13 C20_13 C21_13 C22_13 C23_13 C24_13 C25_13 C26_13 C27_13 C28_13 C29_13 C30_13 C31_13 C32_13 C33_13 C34_13 C35_13 C36_13 C37_13 C38_13 C39_13 C40_13 C41_13 C42_13 R1_13 R2_13 R3_13 R4_13 R5_13 R6_13 R7_13 R8_13 R9_13 R10_13 R11_13 R12_13 R13_13 R14_13 R15_13 R16_13 R17_13 R18_13 R19_13 R20_13 R21_13 TP1_13 TP2_13 U1_13 U2_13 U3_13 U4_13 U5_13 U6_13
component class 13: C1_9 C2_9 C3_9 C4_9 C5_9 C6_9 C7_9 C8_9 C9_9 C10_9 C11_9 C12_9 C13_9 C14_9 C15_9 C16_9 C17_9 C18_9 C19_9 C20_9 C21_9 C22_9 C23_9 C24_9 C25_9 C26_9 C27_9 C28_9 C29_9 C30_9 C31_9 C32_9 C33_9 C34_9 C35_9 C36_9 C37_9 C38_9 C39_9 C40_9 C41_9 C42_9 R1_9 R2_9 R3_9 R4_9 R5_9 R6_9 R7_9 R8_9 R9_9 R10_9 R11_9 R12_9 R13_9 R14_9 R15_9 R16_9 R17_9 R18_9 R19_9 R20_9 R21_9 TP1_9 TP2_9 U1_9 U2_9 U3_9 U4_9 U5_9 U6_9
component class 12: C1_5 C2_5 C3_5 C4_5 C5_5 C6_5 C7_5 C8_5 C9_5 C10_5 C11_5 C12_5 C13_5 C14_5 C15_5 C16_5 C17_5 C18_5 C19_5 C20_5 C21_5 C22_5 C23_5 C24_5 C25_5 C26_5 C27_5 C28_5 C29_5 C30_5 C31_5 C32_5 C33_5 C34_5 C35_5 C36_5 C37_5 C38_5 C39_5 C40_5 C41_5 C42_5 R1_5 R2_5 R3_5 R4_5 R5_5 R6_5 R7_5 R8_5 R9_5 R10_5 R11_5 R12_5 R13_5 R14_5 R15_5 R16_5 R17_5 R18_5 R19_5 R20_5 R21_5 TP1_5 TP2_5 U1_5 U2_5 U3_5 U4_5 U5_5 U6_5
component class 11: C1_1 C2_1 C3_1 C4_1 C5_1 C6_1 C7_1 C8_1 C9_1 C10_1 C11_1 C12_1 C13_1 C14_1 C15_1 C16_1 C17_1 C18_1 C19_1 C20_1 C21_1 C22_1 C23_1 C24_1 C25_1 C26_1 C27_1 C28_1 C29_1 C30_1 C31_1 C32_1 C33_1 C34_1 C35_1 C36_1 C37_1 C38_1 C39_1 C40_1 C41_1 C42_1 R1_1 R2_1 R3_1 R4_1 R5_1 R6_1 R7_1 R8_1 R9_1 R10_1 R11_1 R12_1 R13_1 R14_1 R15_1 R16_1 R17_1 R18_1 R19_1 R20_1 R21_1 TP1_1 TP2_1 U1_1 U2_1 U3_1 U4_1 U5_1 U6_1
channel class ADCTB_QuadADC: 1 2 3 4
channel class ADCTB_Converter: 11 12 13 14 21 22 23 24 31 32 33 34 41 42 43 44
component class 4: C43_4 C44_4 C45_4 C46_4 C94 C96 C120 C121 R22_4 R23_4 R90 R91 U7_4 U8_4 U9_4 U10_4 U30 U31 U32 U33
component class 3: C43_3 C44_3 C45_3 C46_3 C85_3 C86_3 R22_3 R23_3 R38_3 R39_3 U7_3 U8_3 U9_3 U10_3 U11_3
component class 2: C43_2 C44_2 C45_2 C46_2 C85_2 C86_2 R22_2 R23_2 R38_2 R39_2 U7_2 U8_2 U9_2 U10_2 U11_2
component class 1: C43_1 C44_1 C45_1 C46_1 C85_1 C86_1 R22_1 R23_1 R38_1 R39_1 U7_1 U8_1 U9_1 U10_1 U11_1
component class Interface: C44 C45 C46 C82 C83 C84 C85 P1 P2 R24 R25 U11 U12 U13 U14
differential pair CONV: +CONV_P -CONV_N
differential pair CONV4: +CONV4_P -CONV4_N
differential pair CONV3: +CONV3_P -CONV3_N
differential pair CONV2: +CONV2_P -CONV2_N
differential pair CONV1: +CONV1_P -CONV1_N
differential pair BUSY: +BUSY_P -BUSY_N
differential pair ADCOUT16: +ADCOUT16_P -ADCOUT16_N
differential pair ADCOUT15: +ADCOUT15_P -ADCOUT15_N
differential pair ADCOUT14: +ADCOUT14_P -ADCOUT14_N
differential pair ADCOUT13: +ADCOUT13_P -ADCOUT13_N
differential pair ADCOUT12: +ADCOUT12_P -ADCOUT12_N
differential pair ADCOUT11: +ADCOUT11_P -ADCOUT11_N
differential pair ADCOUT10: +ADCOUT10_P -ADCOUT10_N
differential pair ADCOUT9: +ADCOUT9_P -ADCOUT9_N
differential pair ADCOUT8: +ADCOUT8_P -ADCOUT8_N
differential pair ADCOUT7: +ADCOUT7_P -ADCOUT7_N
differential pair ADCOUT6: +ADCOUT6_P -ADCOUT6_N
differential pair ADCOUT5: +ADCOUT5_P -ADCOUT5_N
differential pair ADCOUT4: +ADCOUT4_P -ADCOUT4_N
differential pair ADCOUT3: +ADCOUT3_P -ADCOUT3_N
differential pair ADCOUT2: +ADCOUT2_P -ADCOUT2_N
differential pair ADCLK: +ADCLK_P -ADCLK_N
differential pair ADCLK4: +ADCLK4_P -ADCLK4_N
differential pair ADCLK3: +ADCLK3_P -ADCLK3_N
differential pair ADCLK2: +ADCLK2_P -ADCLK2_N
differential pair ADCLK1: +ADCLK1_P -ADCLK1_N
differential pair ADCOUT1: +ADCOUT1_P -ADCOUT1_N

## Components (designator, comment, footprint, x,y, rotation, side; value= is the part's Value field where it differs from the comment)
C1_1 "1u" CC2013-0805 1300,8925 r180 bottom (schematic designator C1)
C1_2 "1u" CC2013-0805 1300,8375 r180 bottom (schematic designator C1)
C1_3 "1u" CC2013-0805 1300,7825 r180 bottom (schematic designator C1)
C1_4 "1u" CC2013-0805 1300,7275 r180 bottom (schematic designator C1)
C1_5 "1u" CC2013-0805 1300,6725 r180 bottom (schematic designator C1)
C1_6 "1u" CC2013-0805 1300,6175 r180 bottom (schematic designator C1)
C1_7 "1u" CC2013-0805 1300,5625 r180 bottom (schematic designator C1)
C1_8 "1u" CC2013-0805 1300,5075 r180 bottom (schematic designator C1)
C1_9 "1u" CC2013-0805 1300,4525 r180 bottom (schematic designator C1)
C1_10 "1u" CC2013-0805 1300,3975 r180 bottom (schematic designator C1)
C1_11 "1u" CC2013-0805 1300,3425 r180 bottom (schematic designator C1)
C1_12 "1u" CC2013-0805 1300,2875 r180 bottom (schematic designator C1)
C1_13 "1u" CC2013-0805 1300,2325 r180 bottom (schematic designator C1)
C1_14 "1u" CC2013-0805 1300,1775 r180 bottom (schematic designator C1)
C1_15 "1u" CC2013-0805 1300,1225 r180 bottom (schematic designator C1)
C1_16 "1u" CC2013-0805 1300,675 r180 bottom (schematic designator C1)
C2_1 "150p" CC2013-0805 2100,8875 r180 top (schematic designator C2)
C2_2 "150p" CC2013-0805 2100,8325 r180 top (schematic designator C2)
C2_3 "150p" CC2013-0805 2100,7775 r180 top (schematic designator C2)
C2_4 "150p" CC2013-0805 2100,7225 r180 top (schematic designator C2)
C2_5 "150p" CC2013-0805 2100,6675 r180 top (schematic designator C2)
C2_6 "150p" CC2013-0805 2100,6125 r180 top (schematic designator C2)
C2_7 "150p" CC2013-0805 2100,5575 r180 top (schematic designator C2)
C2_8 "150p" CC2013-0805 2100,5025 r180 top (schematic designator C2)
C2_9 "150p" CC2013-0805 2100,4475 r180 top (schematic designator C2)
C2_10 "150p" CC2013-0805 2100,3925 r180 top (schematic designator C2)
C2_11 "150p" CC2013-0805 2100,3375 r180 top (schematic designator C2)
C2_12 "150p" CC2013-0805 2100,2825 r180 top (schematic designator C2)
C2_13 "150p" CC2013-0805 2100,2275 r180 top (schematic designator C2)
C2_14 "150p" CC2013-0805 2100,1725 r180 top (schematic designator C2)
C2_15 "150p" CC2013-0805 2100,1175 r180 top (schematic designator C2)
C2_16 "150p" CC2013-0805 2100,625 r180 top (schematic designator C2)
C3_1 "1u" CC2013-0805 2100,8800 r180 bottom (schematic designator C3)
C3_2 "1u" CC2013-0805 2100,8250 r180 bottom (schematic designator C3)
C3_3 "1u" CC2013-0805 2100,7700 r180 bottom (schematic designator C3)
C3_4 "1u" CC2013-0805 2100,7150 r180 bottom (schematic designator C3)
C3_5 "1u" CC2013-0805 2100,6600 r180 bottom (schematic designator C3)
C3_6 "1u" CC2013-0805 2100,6050 r180 bottom (schematic designator C3)
C3_7 "1u" CC2013-0805 2100,5500 r180 bottom (schematic designator C3)
C3_8 "1u" CC2013-0805 2100,4950 r180 bottom (schematic designator C3)
C3_9 "1u" CC2013-0805 2100,4400 r180 bottom (schematic designator C3)
C3_10 "1u" CC2013-0805 2100,3850 r180 bottom (schematic designator C3)
C3_11 "1u" CC2013-0805 2100,3300 r180 bottom (schematic designator C3)
C3_12 "1u" CC2013-0805 2100,2750 r180 bottom (schematic designator C3)
C3_13 "1u" CC2013-0805 2100,2200 r180 bottom (schematic designator C3)
C3_14 "1u" CC2013-0805 2100,1650 r180 bottom (schematic designator C3)
C3_15 "1u" CC2013-0805 2100,1100 r180 bottom (schematic designator C3)
C3_16 "1u" CC2013-0805 2100,550 r180 bottom (schematic designator C3)
C4_1 "68p" CC2013-0805 1300,8775 r180 bottom (schematic designator C4)
C4_2 "68p" CC2013-0805 1300,8225 r180 bottom (schematic designator C4)
C4_3 "68p" CC2013-0805 1300,7675 r180 bottom (schematic designator C4)
C4_4 "68p" CC2013-0805 1300,7125 r180 bottom (schematic designator C4)
C4_5 "68p" CC2013-0805 1300,6575 r180 bottom (schematic designator C4)
C4_6 "68p" CC2013-0805 1300,6025 r180 bottom (schematic designator C4)
C4_7 "68p" CC2013-0805 1300,5475 r180 bottom (schematic designator C4)
C4_8 "68p" CC2013-0805 1300,4925 r180 bottom (schematic designator C4)
C4_9 "68p" CC2013-0805 1300,4375 r180 bottom (schematic designator C4)
C4_10 "68p" CC2013-0805 1300,3825 r180 bottom (schematic designator C4)
C4_11 "68p" CC2013-0805 1300,3275 r180 bottom (schematic designator C4)
C4_12 "68p" CC2013-0805 1300,2725 r180 bottom (schematic designator C4)
C4_13 "68p" CC2013-0805 1300,2175 r180 bottom (schematic designator C4)
C4_14 "68p" CC2013-0805 1300,1625 r180 bottom (schematic designator C4)
C4_15 "68p" CC2013-0805 1300,1075 r180 bottom (schematic designator C4)
C4_16 "68p" CC2013-0805 1300,525 r180 bottom (schematic designator C4)
C5_1 "1u" CC2013-0805 1000,8725 r180 top (schematic designator C5)
C5_2 "1u" CC2013-0805 1000,8175 r180 top (schematic designator C5)
C5_3 "1u" CC2013-0805 1000,7625 r180 top (schematic designator C5)
C5_4 "1u" CC2013-0805 1000,7075 r180 top (schematic designator C5)
C5_5 "1u" CC2013-0805 1000,6525 r180 top (schematic designator C5)
C5_6 "1u" CC2013-0805 1000,5975 r180 top (schematic designator C5)
C5_7 "1u" CC2013-0805 1000,5425 r180 top (schematic designator C5)
C5_8 "1u" CC2013-0805 1000,4875 r180 top (schematic designator C5)
C5_9 "1u" CC2013-0805 1000,4325 r180 top (schematic designator C5)
C5_10 "1u" CC2013-0805 1000,3775 r180 top (schematic designator C5)
C5_11 "1u" CC2013-0805 1000,3225 r180 top (schematic designator C5)
C5_12 "1u" CC2013-0805 1000,2675 r180 top (schematic designator C5)
C5_13 "1u" CC2013-0805 1000,2125 r180 top (schematic designator C5)
C5_14 "1u" CC2013-0805 1000,1575 r180 top (schematic designator C5)
C5_15 "1u" CC2013-0805 1000,1025 r180 top (schematic designator C5)
C5_16 "1u" CC2013-0805 1000,475 r180 top (schematic designator C5)
C6_1 "2.2n" CC3216-1206 1575,8725 r270 top (schematic designator C6)
C6_2 "2.2n" CC3216-1206 1575,8175 r270 top (schematic designator C6)
C6_3 "2.2n" CC3216-1206 1575,7625 r270 top (schematic designator C6)
C6_4 "2.2n" CC3216-1206 1575,7075 r270 top (schematic designator C6)
C6_5 "2.2n" CC3216-1206 1575,6525 r270 top (schematic designator C6)
C6_6 "2.2n" CC3216-1206 1575,5975 r270 top (schematic designator C6)
C6_7 "2.2n" CC3216-1206 1575,5425 r270 top (schematic designator C6)
C6_8 "2.2n" CC3216-1206 1575,4875 r270 top (schematic designator C6)
C6_9 "2.2n" CC3216-1206 1575,4325 r270 top (schematic designator C6)
C6_10 "2.2n" CC3216-1206 1575,3775 r270 top (schematic designator C6)
C6_11 "2.2n" CC3216-1206 1575,3225 r270 top (schematic designator C6)
C6_12 "2.2n" CC3216-1206 1575,2675 r270 top (schematic designator C6)
C6_13 "2.2n" CC3216-1206 1575,2125 r270 top (schematic designator C6)
C6_14 "2.2n" CC3216-1206 1575,1575 r270 top (schematic designator C6)
C6_15 "2.2n" CC3216-1206 1575,1025 r270 top (schematic designator C6)
C6_16 "2.2n" CC3216-1206 1575,475 r270 top (schematic designator C6)
C7_1 "8.2n" CC3216-1206 1725,8725 r270 top (schematic designator C7)
C7_2 "8.2n" CC3216-1206 1725,8175 r270 top (schematic designator C7)
C7_3 "8.2n" CC3216-1206 1725,7625 r270 top (schematic designator C7)
C7_4 "8.2n" CC3216-1206 1725,7075 r270 top (schematic designator C7)
C7_5 "8.2n" CC3216-1206 1725,6525 r270 top (schematic designator C7)
C7_6 "8.2n" CC3216-1206 1725,5975 r270 top (schematic designator C7)
C7_7 "8.2n" CC3216-1206 1725,5425 r270 top (schematic designator C7)
C7_8 "8.2n" CC3216-1206 1725,4875 r270 top (schematic designator C7)
C7_9 "8.2n" CC3216-1206 1725,4325 r270 top (schematic designator C7)
C7_10 "8.2n" CC3216-1206 1725,3775 r270 top (schematic designator C7)
C7_11 "8.2n" CC3216-1206 1725,3225 r270 top (schematic designator C7)
C7_12 "8.2n" CC3216-1206 1725,2675 r270 top (schematic designator C7)
C7_13 "8.2n" CC3216-1206 1725,2125 r270 top (schematic designator C7)
C7_14 "8.2n" CC3216-1206 1725,1575 r270 top (schematic designator C7)
C7_15 "8.2n" CC3216-1206 1725,1025 r270 top (schematic designator C7)
C7_16 "8.2n" CC3216-1206 1725,475 r270 top (schematic designator C7)
C8_1 "1u" CC2013-0805 1000,8525 r180 top (schematic designator C8)
C8_2 "1u" CC2013-0805 1000,7975 r180 top (schematic designator C8)
C8_3 "1u" CC2013-0805 1000,7425 r180 top (schematic designator C8)
C8_4 "1u" CC2013-0805 1000,6875 r180 top (schematic designator C8)
C8_5 "1u" CC2013-0805 1000,6325 r180 top (schematic designator C8)
C8_6 "1u" CC2013-0805 1000,5775 r180 top (schematic designator C8)
C8_7 "1u" CC2013-0805 1000,5225 r180 top (schematic designator C8)
C8_8 "1u" CC2013-0805 1000,4675 r180 top (schematic designator C8)
C8_9 "1u" CC2013-0805 1000,4125 r180 top (schematic designator C8)
C8_10 "1u" CC2013-0805 1000,3575 r180 top (schematic designator C8)
C8_11 "1u" CC2013-0805 1000,3025 r180 top (schematic designator C8)
C8_12 "1u" CC2013-0805 1000,2475 r180 top (schematic designator C8)
C8_13 "1u" CC2013-0805 1000,1925 r180 top (schematic designator C8)
C8_14 "1u" CC2013-0805 1000,1375 r180 top (schematic designator C8)
C8_15 "1u" CC2013-0805 1000,825 r180 top (schematic designator C8)
C8_16 "1u" CC2013-0805 1000,275 r180 top (schematic designator C8)
C9_1 "68p" CC2013-0805 2100,8725 r180 bottom (schematic designator C9)
C9_2 "68p" CC2013-0805 2100,8175 r180 bottom (schematic designator C9)
C9_3 "68p" CC2013-0805 2100,7625 r180 bottom (schematic designator C9)
C9_4 "68p" CC2013-0805 2100,7075 r180 bottom (schematic designator C9)
C9_5 "68p" CC2013-0805 2100,6525 r180 bottom (schematic designator C9)
C9_6 "68p" CC2013-0805 2100,5975 r180 bottom (schematic designator C9)
C9_7 "68p" CC2013-0805 2100,5425 r180 bottom (schematic designator C9)
C9_8 "68p" CC2013-0805 2100,4875 r180 bottom (schematic designator C9)
C9_9 "68p" CC2013-0805 2100,4325 r180 bottom (schematic designator C9)
C9_10 "68p" CC2013-0805 2100,3775 r180 bottom (schematic designator C9)
C9_11 "68p" CC2013-0805 2100,3225 r180 bottom (schematic designator C9)
C9_12 "68p" CC2013-0805 2100,2675 r180 bottom (schematic designator C9)
C9_13 "68p" CC2013-0805 2100,2125 r180 bottom (schematic designator C9)
C9_14 "68p" CC2013-0805 2100,1575 r180 bottom (schematic designator C9)
C9_15 "68p" CC2013-0805 2100,1025 r180 bottom (schematic designator C9)
C9_16 "68p" CC2013-0805 2100,475 r180 bottom (schematic designator C9)
C10_1 "1u" CC2013-0805 2100,8650 r0 bottom (schematic designator C10)
C10_2 "1u" CC2013-0805 2100,8100 r0 bottom (schematic designator C10)
C10_3 "1u" CC2013-0805 2100,7550 r0 bottom (schematic designator C10)
C10_4 "1u" CC2013-0805 2100,7000 r0 bottom (schematic designator C10)
C10_5 "1u" CC2013-0805 2100,6450 r0 bottom (schematic designator C10)
C10_6 "1u" CC2013-0805 2100,5900 r0 bottom (schematic designator C10)
C10_7 "1u" CC2013-0805 2100,5350 r0 bottom (schematic designator C10)
C10_8 "1u" CC2013-0805 2100,4800 r0 bottom (schematic designator C10)
C10_9 "1u" CC2013-0805 2100,4250 r0 bottom (schematic designator C10)
C10_10 "1u" CC2013-0805 2100,3700 r0 bottom (schematic designator C10)
C10_11 "1u" CC2013-0805 2100,3150 r0 bottom (schematic designator C10)
C10_12 "1u" CC2013-0805 2100,2600 r0 bottom (schematic designator C10)
C10_13 "1u" CC2013-0805 2100,2050 r0 bottom (schematic designator C10)
C10_14 "1u" CC2013-0805 2100,1500 r0 bottom (schematic designator C10)
C10_15 "1u" CC2013-0805 2100,950 r0 bottom (schematic designator C10)
C10_16 "1u" CC2013-0805 2100,400 r0 bottom (schematic designator C10)
C11_1 "68p" CC2013-0805 1300,8525 r180 bottom (schematic designator C11)
C11_2 "68p" CC2013-0805 1300,7975 r180 bottom (schematic designator C11)
C11_3 "68p" CC2013-0805 1300,7425 r180 bottom (schematic designator C11)
C11_4 "68p" CC2013-0805 1300,6875 r180 bottom (schematic designator C11)
C11_5 "68p" CC2013-0805 1300,6325 r180 bottom (schematic designator C11)
C11_6 "68p" CC2013-0805 1300,5775 r180 bottom (schematic designator C11)
C11_7 "68p" CC2013-0805 1300,5225 r180 bottom (schematic designator C11)
C11_8 "68p" CC2013-0805 1300,4675 r180 bottom (schematic designator C11)
C11_9 "68p" CC2013-0805 1300,4125 r180 bottom (schematic designator C11)
C11_10 "68p" CC2013-0805 1300,3575 r180 bottom (schematic designator C11)
C11_11 "68p" CC2013-0805 1300,3025 r180 bottom (schematic designator C11)
C11_12 "68p" CC2013-0805 1300,2475 r180 bottom (schematic designator C11)
C11_13 "68p" CC2013-0805 1300,1925 r180 bottom (schematic designator C11)
C11_14 "68p" CC2013-0805 1300,1375 r180 bottom (schematic designator C11)
C11_15 "68p" CC2013-0805 1300,825 r180 bottom (schematic designator C11)
C11_16 "68p" CC2013-0805 1300,275 r180 bottom (schematic designator C11)
C12_1 "150p" CC2013-0805 2100,8575 r180 top (schematic designator C12)
C12_2 "150p" CC2013-0805 2100,8025 r180 top (schematic designator C12)
C12_3 "150p" CC2013-0805 2100,7475 r180 top (schematic designator C12)
C12_4 "150p" CC2013-0805 2100,6925 r180 top (schematic designator C12)
C12_5 "150p" CC2013-0805 2100,6375 r180 top (schematic designator C12)
C12_6 "150p" CC2013-0805 2100,5825 r180 top (schematic designator C12)
C12_7 "150p" CC2013-0805 2100,5275 r180 top (schematic designator C12)
C12_8 "150p" CC2013-0805 2100,4725 r180 top (schematic designator C12)
C12_9 "150p" CC2013-0805 2100,4175 r180 top (schematic designator C12)
C12_10 "150p" CC2013-0805 2100,3625 r180 top (schematic designator C12)
C12_11 "150p" CC2013-0805 2100,3075 r180 top (schematic designator C12)
C12_12 "150p" CC2013-0805 2100,2525 r180 top (schematic designator C12)
C12_13 "150p" CC2013-0805 2100,1975 r180 top (schematic designator C12)
C12_14 "150p" CC2013-0805 2100,1425 r180 top (schematic designator C12)
C12_15 "150p" CC2013-0805 2100,875 r180 top (schematic designator C12)
C12_16 "150p" CC2013-0805 2100,325 r180 top (schematic designator C12)
C13_1 "10u" CC3216-1206 3425,8800 r180 bottom (schematic designator C13)
C13_2 "10u" CC3216-1206 3425,8250 r180 bottom (schematic designator C13)
C13_3 "10u" CC3216-1206 3425,7700 r180 bottom (schematic designator C13)
C13_4 "10u" CC3216-1206 3425,7150 r180 bottom (schematic designator C13)
C13_5 "10u" CC3216-1206 3425,6600 r180 bottom (schematic designator C13)
C13_6 "10u" CC3216-1206 3425,6050 r180 bottom (schematic designator C13)
C13_7 "10u" CC3216-1206 3425,5500 r180 bottom (schematic designator C13)
C13_8 "10u" CC3216-1206 3425,4950 r180 bottom (schematic designator C13)
C13_9 "10u" CC3216-1206 3425,4400 r180 bottom (schematic designator C13)
C13_10 "10u" CC3216-1206 3425,3850 r180 bottom (schematic designator C13)
C13_11 "10u" CC3216-1206 3425,3300 r180 bottom (schematic designator C13)
C13_12 "10u" CC3216-1206 3425,2750 r180 bottom (schematic designator C13)
C13_13 "10u" CC3216-1206 3425,2200 r180 bottom (schematic designator C13)
C13_14 "10u" CC3216-1206 3425,1650 r180 bottom (schematic designator C13)
C13_15 "10u" CC3216-1206 3425,1100 r180 bottom (schematic designator C13)
C13_16 "10u" CC3216-1206 3425,550 r180 bottom (schematic designator C13)
C14_1 "1u" CC2013-0805 3450,8725 r180 bottom (schematic designator C14)
C14_2 "1u" CC2013-0805 3450,8175 r180 bottom (schematic designator C14)
C14_3 "1u" CC2013-0805 3450,7625 r180 bottom (schematic designator C14)
C14_4 "1u" CC2013-0805 3450,7075 r180 bottom (schematic designator C14)
C14_5 "1u" CC2013-0805 3450,6525 r180 bottom (schematic designator C14)
C14_6 "1u" CC2013-0805 3450,5975 r180 bottom (schematic designator C14)
C14_7 "1u" CC2013-0805 3450,5425 r180 bottom (schematic designator C14)
C14_8 "1u" CC2013-0805 3450,4875 r180 bottom (schematic designator C14)
C14_9 "1u" CC2013-0805 3450,4325 r180 bottom (schematic designator C14)
C14_10 "1u" CC2013-0805 3450,3775 r180 bottom (schematic designator C14)
C14_11 "1u" CC2013-0805 3450,3225 r180 bottom (schematic designator C14)
C14_12 "1u" CC2013-0805 3450,2675 r180 bottom (schematic designator C14)
C14_13 "1u" CC2013-0805 3450,2125 r180 bottom (schematic designator C14)
C14_14 "1u" CC2013-0805 3450,1575 r180 bottom (schematic designator C14)
C14_15 "1u" CC2013-0805 3450,1025 r180 bottom (schematic designator C14)
C14_16 "1u" CC2013-0805 3450,475 r180 bottom (schematic designator C14)
C15_1 "100n" CC2013-0805 3450,8650 r180 bottom (schematic designator C15)
C15_2 "100n" CC2013-0805 3450,8100 r180 bottom (schematic designator C15)
C15_3 "100n" CC2013-0805 3450,7550 r180 bottom (schematic designator C15)
C15_4 "100n" CC2013-0805 3450,7000 r180 bottom (schematic designator C15)
C15_5 "100n" CC2013-0805 3450,6450 r180 bottom (schematic designator C15)
C15_6 "100n" CC2013-0805 3450,5900 r180 bottom (schematic designator C15)
C15_7 "100n" CC2013-0805 3450,5350 r180 bottom (schematic designator C15)
C15_8 "100n" CC2013-0805 3450,4800 r180 bottom (schematic designator C15)
C15_9 "100n" CC2013-0805 3450,4250 r180 bottom (schematic designator C15)
C15_10 "100n" CC2013-0805 3450,3700 r180 bottom (schematic designator C15)
C15_11 "100n" CC2013-0805 3450,3150 r180 bottom (schematic designator C15)
C15_12 "100n" CC2013-0805 3450,2600 r180 bottom (schematic designator C15)
C15_13 "100n" CC2013-0805 3450,2050 r180 bottom (schematic designator C15)
C15_14 "100n" CC2013-0805 3450,1500 r180 bottom (schematic designator C15)
C15_15 "100n" CC2013-0805 3450,950 r180 bottom (schematic designator C15)
C15_16 "100n" CC2013-0805 3450,400 r180 bottom (schematic designator C15)
C16_1 "100n" CC2013-0805 3750,8800 r180 bottom (schematic designator C16)
C16_2 "100n" CC2013-0805 3750,8250 r180 bottom (schematic designator C16)
C16_3 "100n" CC2013-0805 3750,7700 r180 bottom (schematic designator C16)
C16_4 "100n" CC2013-0805 3750,7150 r180 bottom (schematic designator C16)
C16_5 "100n" CC2013-0805 3750,6600 r180 bottom (schematic designator C16)
C16_6 "100n" CC2013-0805 3750,6050 r180 bottom (schematic designator C16)
C16_7 "100n" CC2013-0805 3750,5500 r180 bottom (schematic designator C16)
C16_8 "100n" CC2013-0805 3750,4950 r180 bottom (schematic designator C16)
C16_9 "100n" CC2013-0805 3750,4400 r180 bottom (schematic designator C16)
C16_10 "100n" CC2013-0805 3750,3850 r180 bottom (schematic designator C16)
C16_11 "100n" CC2013-0805 3750,3300 r180 bottom (schematic designator C16)
C16_12 "100n" CC2013-0805 3750,2750 r180 bottom (schematic designator C16)
C16_13 "100n" CC2013-0805 3750,2200 r180 bottom (schematic designator C16)
C16_14 "100n" CC2013-0805 3750,1650 r180 bottom (schematic designator C16)
C16_15 "100n" CC2013-0805 3750,1100 r180 bottom (schematic designator C16)
C16_16 "100n" CC2013-0805 3750,550 r180 bottom (schematic designator C16)
C17_1 "1u" CC2013-0805 3750,8875 r180 bottom (schematic designator C17)
C17_2 "1u" CC2013-0805 3750,8325 r180 bottom (schematic designator C17)
C17_3 "1u" CC2013-0805 3750,7775 r180 bottom (schematic designator C17)
C17_4 "1u" CC2013-0805 3750,7225 r180 bottom (schematic designator C17)
C17_5 "1u" CC2013-0805 3750,6675 r180 bottom (schematic designator C17)
C17_6 "1u" CC2013-0805 3750,6125 r180 bottom (schematic designator C17)
C17_7 "1u" CC2013-0805 3750,5575 r180 bottom (schematic designator C17)
C17_8 "1u" CC2013-0805 3750,5025 r180 bottom (schematic designator C17)
C17_9 "1u" CC2013-0805 3750,4475 r180 bottom (schematic designator C17)
C17_10 "1u" CC2013-0805 3750,3925 r180 bottom (schematic designator C17)
C17_11 "1u" CC2013-0805 3750,3375 r180 bottom (schematic designator C17)
C17_12 "1u" CC2013-0805 3750,2825 r180 bottom (schematic designator C17)
C17_13 "1u" CC2013-0805 3750,2275 r180 bottom (schematic designator C17)
C17_14 "1u" CC2013-0805 3750,1725 r180 bottom (schematic designator C17)
C17_15 "1u" CC2013-0805 3750,1175 r180 bottom (schematic designator C17)
C17_16 "1u" CC2013-0805 3750,625 r180 bottom (schematic designator C17)
C18_1 "10u" CC3216-1206 3725,8950 r180 bottom (schematic designator C18)
C18_2 "10u" CC3216-1206 3725,8400 r180 bottom (schematic designator C18)
C18_3 "10u" CC3216-1206 3725,7850 r180 bottom (schematic designator C18)
C18_4 "10u" CC3216-1206 3725,7300 r180 bottom (schematic designator C18)
C18_5 "10u" CC3216-1206 3725,6750 r180 bottom (schematic designator C18)
C18_6 "10u" CC3216-1206 3725,6200 r180 bottom (schematic designator C18)
C18_7 "10u" CC3216-1206 3725,5650 r180 bottom (schematic designator C18)
C18_8 "10u" CC3216-1206 3725,5100 r180 bottom (schematic designator C18)
C18_9 "10u" CC3216-1206 3725,4550 r180 bottom (schematic designator C18)
C18_10 "10u" CC3216-1206 3725,4000 r180 bottom (schematic designator C18)
C18_11 "10u" CC3216-1206 3725,3450 r180 bottom (schematic designator C18)
C18_12 "10u" CC3216-1206 3725,2900 r180 bottom (schematic designator C18)
C18_13 "10u" CC3216-1206 3725,2350 r180 bottom (schematic designator C18)
C18_14 "10u" CC3216-1206 3725,1800 r180 bottom (schematic designator C18)
C18_15 "10u" CC3216-1206 3725,1250 r180 bottom (schematic designator C18)
C18_16 "10u" CC3216-1206 3725,700 r180 bottom (schematic designator C18)
C19_1 "1u" CC2013-0805 1300,8675 r180 bottom (schematic designator C19)
C19_2 "1u" CC2013-0805 1300,8125 r180 bottom (schematic designator C19)
C19_3 "1u" CC2013-0805 1300,7575 r180 bottom (schematic designator C19)
C19_4 "1u" CC2013-0805 1300,7025 r180 bottom (schematic designator C19)
C19_5 "1u" CC2013-0805 1300,6475 r180 bottom (schematic designator C19)
C19_6 "1u" CC2013-0805 1300,5925 r180 bottom (schematic designator C19)
C19_7 "1u" CC2013-0805 1300,5375 r180 bottom (schematic designator C19)
C19_8 "1u" CC2013-0805 1300,4825 r180 bottom (schematic designator C19)
C19_9 "1u" CC2013-0805 1300,4275 r180 bottom (schematic designator C19)
C19_10 "1u" CC2013-0805 1300,3725 r180 bottom (schematic designator C19)
C19_11 "1u" CC2013-0805 1300,3175 r180 bottom (schematic designator C19)
C19_12 "1u" CC2013-0805 1300,2625 r180 bottom (schematic designator C19)
C19_13 "1u" CC2013-0805 1300,2075 r180 bottom (schematic designator C19)
C19_14 "1u" CC2013-0805 1300,1525 r180 bottom (schematic designator C19)
C19_15 "1u" CC2013-0805 1300,975 r180 bottom (schematic designator C19)
C19_16 "1u" CC2013-0805 1300,425 r180 bottom (schematic designator C19)
C20_1 "10u" CC3216-1206 3250,8925 r0 bottom (schematic designator C20)
C20_2 "10u" CC3216-1206 3250,8375 r0 bottom (schematic designator C20)
C20_3 "10u" CC3216-1206 3250,7825 r0 bottom (schematic designator C20)
C20_4 "10u" CC3216-1206 3250,7275 r0 bottom (schematic designator C20)
C20_5 "10u" CC3216-1206 3250,6725 r0 bottom (schematic designator C20)
C20_6 "10u" CC3216-1206 3250,6175 r0 bottom (schematic designator C20)
C20_7 "10u" CC3216-1206 3250,5625 r0 bottom (schematic designator C20)
C20_8 "10u" CC3216-1206 3250,5075 r0 bottom (schematic designator C20)
C20_9 "10u" CC3216-1206 3250,4525 r0 bottom (schematic designator C20)
C20_10 "10u" CC3216-1206 3250,3975 r0 bottom (schematic designator C20)
C20_11 "10u" CC3216-1206 3250,3425 r0 bottom (schematic designator C20)
C20_12 "10u" CC3216-1206 3250,2875 r0 bottom (schematic designator C20)
C20_13 "10u" CC3216-1206 3250,2325 r0 bottom (schematic designator C20)
C20_14 "10u" CC3216-1206 3250,1775 r0 bottom (schematic designator C20)
C20_15 "10u" CC3216-1206 3250,1225 r0 bottom (schematic designator C20)
C20_16 "10u" CC3216-1206 3250,675 r0 bottom (schematic designator C20)
C21_1 "1u" CC2013-0805 3225,8775 r0 bottom (schematic designator C21)
C21_2 "1u" CC2013-0805 3225,8225 r0 bottom (schematic designator C21)
C21_3 "1u" CC2013-0805 3225,7675 r0 bottom (schematic designator C21)
C21_4 "1u" CC2013-0805 3225,7125 r0 bottom (schematic designator C21)
C21_5 "1u" CC2013-0805 3225,6575 r0 bottom (schematic designator C21)
C21_6 "1u" CC2013-0805 3225,6025 r0 bottom (schematic designator C21)
C21_7 "1u" CC2013-0805 3225,5475 r0 bottom (schematic designator C21)
C21_8 "1u" CC2013-0805 3225,4925 r0 bottom (schematic designator C21)
C21_9 "1u" CC2013-0805 3225,4375 r0 bottom (schematic designator C21)
C21_10 "1u" CC2013-0805 3225,3825 r0 bottom (schematic designator C21)
C21_11 "1u" CC2013-0805 3225,3275 r0 bottom (schematic designator C21)
C21_12 "1u" CC2013-0805 3225,2725 r0 bottom (schematic designator C21)
C21_13 "1u" CC2013-0805 3225,2175 r0 bottom (schematic designator C21)
C21_14 "1u" CC2013-0805 3225,1625 r0 bottom (schematic designator C21)
C21_15 "1u" CC2013-0805 3225,1075 r0 bottom (schematic designator C21)
C21_16 "1u" CC2013-0805 3225,525 r0 bottom (schematic designator C21)
C22_1 "100n" CC2013-0805 3225,8850 r0 bottom (schematic designator C22)
C22_2 "100n" CC2013-0805 3225,8300 r0 bottom (schematic designator C22)
C22_3 "100n" CC2013-0805 3225,7750 r0 bottom (schematic designator C22)
C22_4 "100n" CC2013-0805 3225,7200 r0 bottom (schematic designator C22)
C22_5 "100n" CC2013-0805 3225,6650 r0 bottom (schematic designator C22)
C22_6 "100n" CC2013-0805 3225,6100 r0 bottom (schematic designator C22)
C22_7 "100n" CC2013-0805 3225,5550 r0 bottom (schematic designator C22)
C22_8 "100n" CC2013-0805 3225,5000 r0 bottom (schematic designator C22)
C22_9 "100n" CC2013-0805 3225,4450 r0 bottom (schematic designator C22)
C22_10 "100n" CC2013-0805 3225,3900 r0 bottom (schematic designator C22)
C22_11 "100n" CC2013-0805 3225,3350 r0 bottom (schematic designator C22)
C22_12 "100n" CC2013-0805 3225,2800 r0 bottom (schematic designator C22)
C22_13 "100n" CC2013-0805 3225,2250 r0 bottom (schematic designator C22)
C22_14 "100n" CC2013-0805 3225,1700 r0 bottom (schematic designator C22)
C22_15 "100n" CC2013-0805 3225,1150 r0 bottom (schematic designator C22)
C22_16 "100n" CC2013-0805 3225,600 r0 bottom (schematic designator C22)
C23_1 "100n" CC2013-0805 3750,8575 r180 bottom (schematic designator C23)
C23_2 "100n" CC2013-0805 3750,8025 r180 bottom (schematic designator C23)
C23_3 "100n" CC2013-0805 3750,7475 r180 bottom (schematic designator C23)
C23_4 "100n" CC2013-0805 3750,6925 r180 bottom (schematic designator C23)
C23_5 "100n" CC2013-0805 3750,6375 r180 bottom (schematic designator C23)
C23_6 "100n" CC2013-0805 3750,5825 r180 bottom (schematic designator C23)
C23_7 "100n" CC2013-0805 3750,5275 r180 bottom (schematic designator C23)
C23_8 "100n" CC2013-0805 3750,4725 r180 bottom (schematic designator C23)
C23_9 "100n" CC2013-0805 3750,4175 r180 bottom (schematic designator C23)
C23_10 "100n" CC2013-0805 3750,3625 r180 bottom (schematic designator C23)
C23_11 "100n" CC2013-0805 3750,3075 r180 bottom (schematic designator C23)
C23_12 "100n" CC2013-0805 3750,2525 r180 bottom (schematic designator C23)
C23_13 "100n" CC2013-0805 3750,1975 r180 bottom (schematic designator C23)
C23_14 "100n" CC2013-0805 3750,1425 r180 bottom (schematic designator C23)
C23_15 "100n" CC2013-0805 3750,875 r180 bottom (schematic designator C23)
C23_16 "100n" CC2013-0805 3750,325 r180 bottom (schematic designator C23)
C24_1 "1u" CC2013-0805 3750,8650 r180 bottom (schematic designator C24)
C24_2 "1u" CC2013-0805 3750,8100 r180 bottom (schematic designator C24)
C24_3 "1u" CC2013-0805 3750,7550 r180 bottom (schematic designator C24)
C24_4 "1u" CC2013-0805 3750,7000 r180 bottom (schematic designator C24)
C24_5 "1u" CC2013-0805 3750,6450 r180 bottom (schematic designator C24)
C24_6 "1u" CC2013-0805 3750,5900 r180 bottom (schematic designator C24)
C24_7 "1u" CC2013-0805 3750,5350 r180 bottom (schematic designator C24)
C24_8 "1u" CC2013-0805 3750,4800 r180 bottom (schematic designator C24)
C24_9 "1u" CC2013-0805 3750,4250 r180 bottom (schematic designator C24)
C24_10 "1u" CC2013-0805 3750,3700 r180 bottom (schematic designator C24)
C24_11 "1u" CC2013-0805 3750,3150 r180 bottom (schematic designator C24)
C24_12 "1u" CC2013-0805 3750,2600 r180 bottom (schematic designator C24)
C24_13 "1u" CC2013-0805 3750,2050 r180 bottom (schematic designator C24)
C24_14 "1u" CC2013-0805 3750,1500 r180 bottom (schematic designator C24)
C24_15 "1u" CC2013-0805 3750,950 r180 bottom (schematic designator C24)
C24_16 "1u" CC2013-0805 3750,400 r180 bottom (schematic designator C24)
C25_1 "10u" CC3216-1206 3725,8500 r180 bottom (schematic designator C25)
C25_2 "10u" CC3216-1206 3725,7950 r180 bottom (schematic designator C25)
C25_3 "10u" CC3216-1206 3725,7400 r180 bottom (schematic designator C25)
C25_4 "10u" CC3216-1206 3725,6850 r180 bottom (schematic designator C25)
C25_5 "10u" CC3216-1206 3725,6300 r180 bottom (schematic designator C25)
C25_6 "10u" CC3216-1206 3725,5750 r180 bottom (schematic designator C25)
C25_7 "10u" CC3216-1206 3725,5200 r180 bottom (schematic designator C25)
C25_8 "10u" CC3216-1206 3725,4650 r180 bottom (schematic designator C25)
C25_9 "10u" CC3216-1206 3725,4100 r180 bottom (schematic designator C25)
C25_10 "10u" CC3216-1206 3725,3550 r180 bottom (schematic designator C25)
C25_11 "10u" CC3216-1206 3725,3000 r180 bottom (schematic designator C25)
C25_12 "10u" CC3216-1206 3725,2450 r180 bottom (schematic designator C25)
C25_13 "10u" CC3216-1206 3725,1900 r180 bottom (schematic designator C25)
C25_14 "10u" CC3216-1206 3725,1350 r180 bottom (schematic designator C25)
C25_15 "10u" CC3216-1206 3725,800 r180 bottom (schematic designator C25)
C25_16 "10u" CC3216-1206 3725,250 r180 bottom (schematic designator C25)
C26_1 "NL" CC2013-0805 3150,8525 r180 top (schematic designator C26)
C26_2 "NL" CC2013-0805 3150,7975 r180 top (schematic designator C26)
C26_3 "NL" CC2013-0805 3150,7425 r180 top (schematic designator C26)
C26_4 "NL" CC2013-0805 3150,6875 r180 top (schematic designator C26)
C26_5 "NL" CC2013-0805 3150,6325 r180 top (schematic designator C26)
C26_6 "NL" CC2013-0805 3150,5775 r180 top (schematic designator C26)
C26_7 "NL" CC2013-0805 3150,5225 r180 top (schematic designator C26)
C26_8 "NL" CC2013-0805 3150,4675 r180 top (schematic designator C26)
C26_9 "NL" CC2013-0805 3150,4125 r180 top (schematic designator C26)
C26_10 "NL" CC2013-0805 3150,3575 r180 top (schematic designator C26)
C26_11 "NL" CC2013-0805 3150,3025 r180 top (schematic designator C26)
C26_12 "NL" CC2013-0805 3150,2475 r180 top (schematic designator C26)
C26_13 "NL" CC2013-0805 3150,1925 r180 top (schematic designator C26)
C26_14 "NL" CC2013-0805 3150,1375 r180 top (schematic designator C26)
C26_15 "NL" CC2013-0805 3150,825 r180 top (schematic designator C26)
C26_16 "NL" CC2013-0805 3150,275 r180 top (schematic designator C26)
C27_1 "10n" CC3216-1206 2825,8700 r180 bottom (schematic designator C27)
C27_2 "10n" CC3216-1206 2825,8150 r180 bottom (schematic designator C27)
C27_3 "10n" CC3216-1206 2825,7600 r180 bottom (schematic designator C27)
C27_4 "10n" CC3216-1206 2825,7050 r180 bottom (schematic designator C27)
C27_5 "10n" CC3216-1206 2825,6500 r180 bottom (schematic designator C27)
C27_6 "10n" CC3216-1206 2825,5950 r180 bottom (schematic designator C27)
C27_7 "10n" CC3216-1206 2825,5400 r180 bottom (schematic designator C27)
C27_8 "10n" CC3216-1206 2825,4850 r180 bottom (schematic designator C27)
C27_9 "10n" CC3216-1206 2825,4300 r180 bottom (schematic designator C27)
C27_10 "10n" CC3216-1206 2825,3750 r180 bottom (schematic designator C27)
C27_11 "10n" CC3216-1206 2825,3200 r180 bottom (schematic designator C27)
C27_12 "10n" CC3216-1206 2825,2650 r180 bottom (schematic designator C27)
C27_13 "10n" CC3216-1206 2825,2100 r180 bottom (schematic designator C27)
C27_14 "10n" CC3216-1206 2825,1550 r180 bottom (schematic designator C27)
C27_15 "10n" CC3216-1206 2825,1000 r180 bottom (schematic designator C27)
C27_16 "10n" CC3216-1206 2825,450 r180 bottom (schematic designator C27)
C28_1 "1u" CC2013-0805 2550,8525 r180 top (schematic designator C28)
C28_2 "1u" CC2013-0805 2550,7975 r180 top (schematic designator C28)
C28_3 "1u" CC2013-0805 2550,7425 r180 top (schematic designator C28)
C28_4 "1u" CC2013-0805 2550,6875 r180 top (schematic designator C28)
C28_5 "1u" CC2013-0805 2550,6325 r180 top (schematic designator C28)
C28_6 "1u" CC2013-0805 2550,5775 r180 top (schematic designator C28)
C28_7 "1u" CC2013-0805 2550,5225 r180 top (schematic designator C28)
C28_8 "1u" CC2013-0805 2550,4675 r180 top (schematic designator C28)
C28_9 "1u" CC2013-0805 2550,4125 r180 top (schematic designator C28)
C28_10 "1u" CC2013-0805 2550,3575 r180 top (schematic designator C28)
C28_11 "1u" CC2013-0805 2550,3025 r180 top (schematic designator C28)
C28_12 "1u" CC2013-0805 2550,2475 r180 top (schematic designator C28)
C28_13 "1u" CC2013-0805 2550,1925 r180 top (schematic designator C28)
C28_14 "1u" CC2013-0805 2550,1375 r180 top (schematic designator C28)
C28_15 "1u" CC2013-0805 2550,825 r180 top (schematic designator C28)
C28_16 "1u" CC2013-0805 2550,275 r180 top (schematic designator C28)
C29_1 "1u" CC2013-0805 2850,8925 r180 bottom (schematic designator C29)
C29_2 "1u" CC2013-0805 2850,8375 r180 bottom (schematic designator C29)
C29_3 "1u" CC2013-0805 2850,7825 r180 bottom (schematic designator C29)
C29_4 "1u" CC2013-0805 2850,7275 r180 bottom (schematic designator C29)
C29_5 "1u" CC2013-0805 2850,6725 r180 bottom (schematic designator C29)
